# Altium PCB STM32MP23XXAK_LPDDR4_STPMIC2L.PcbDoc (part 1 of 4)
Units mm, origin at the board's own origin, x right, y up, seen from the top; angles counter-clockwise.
Board outline 120 x 79.6 mm, 4 copper layers (Top Layer, Signal Layer 1, Signal Layer 2, Bottom Layer), stack 1.614 mm thick; 156 components, 124 nets, 1131 pads, 692 vias.
Unrouted connection lines stored in the file: 3.
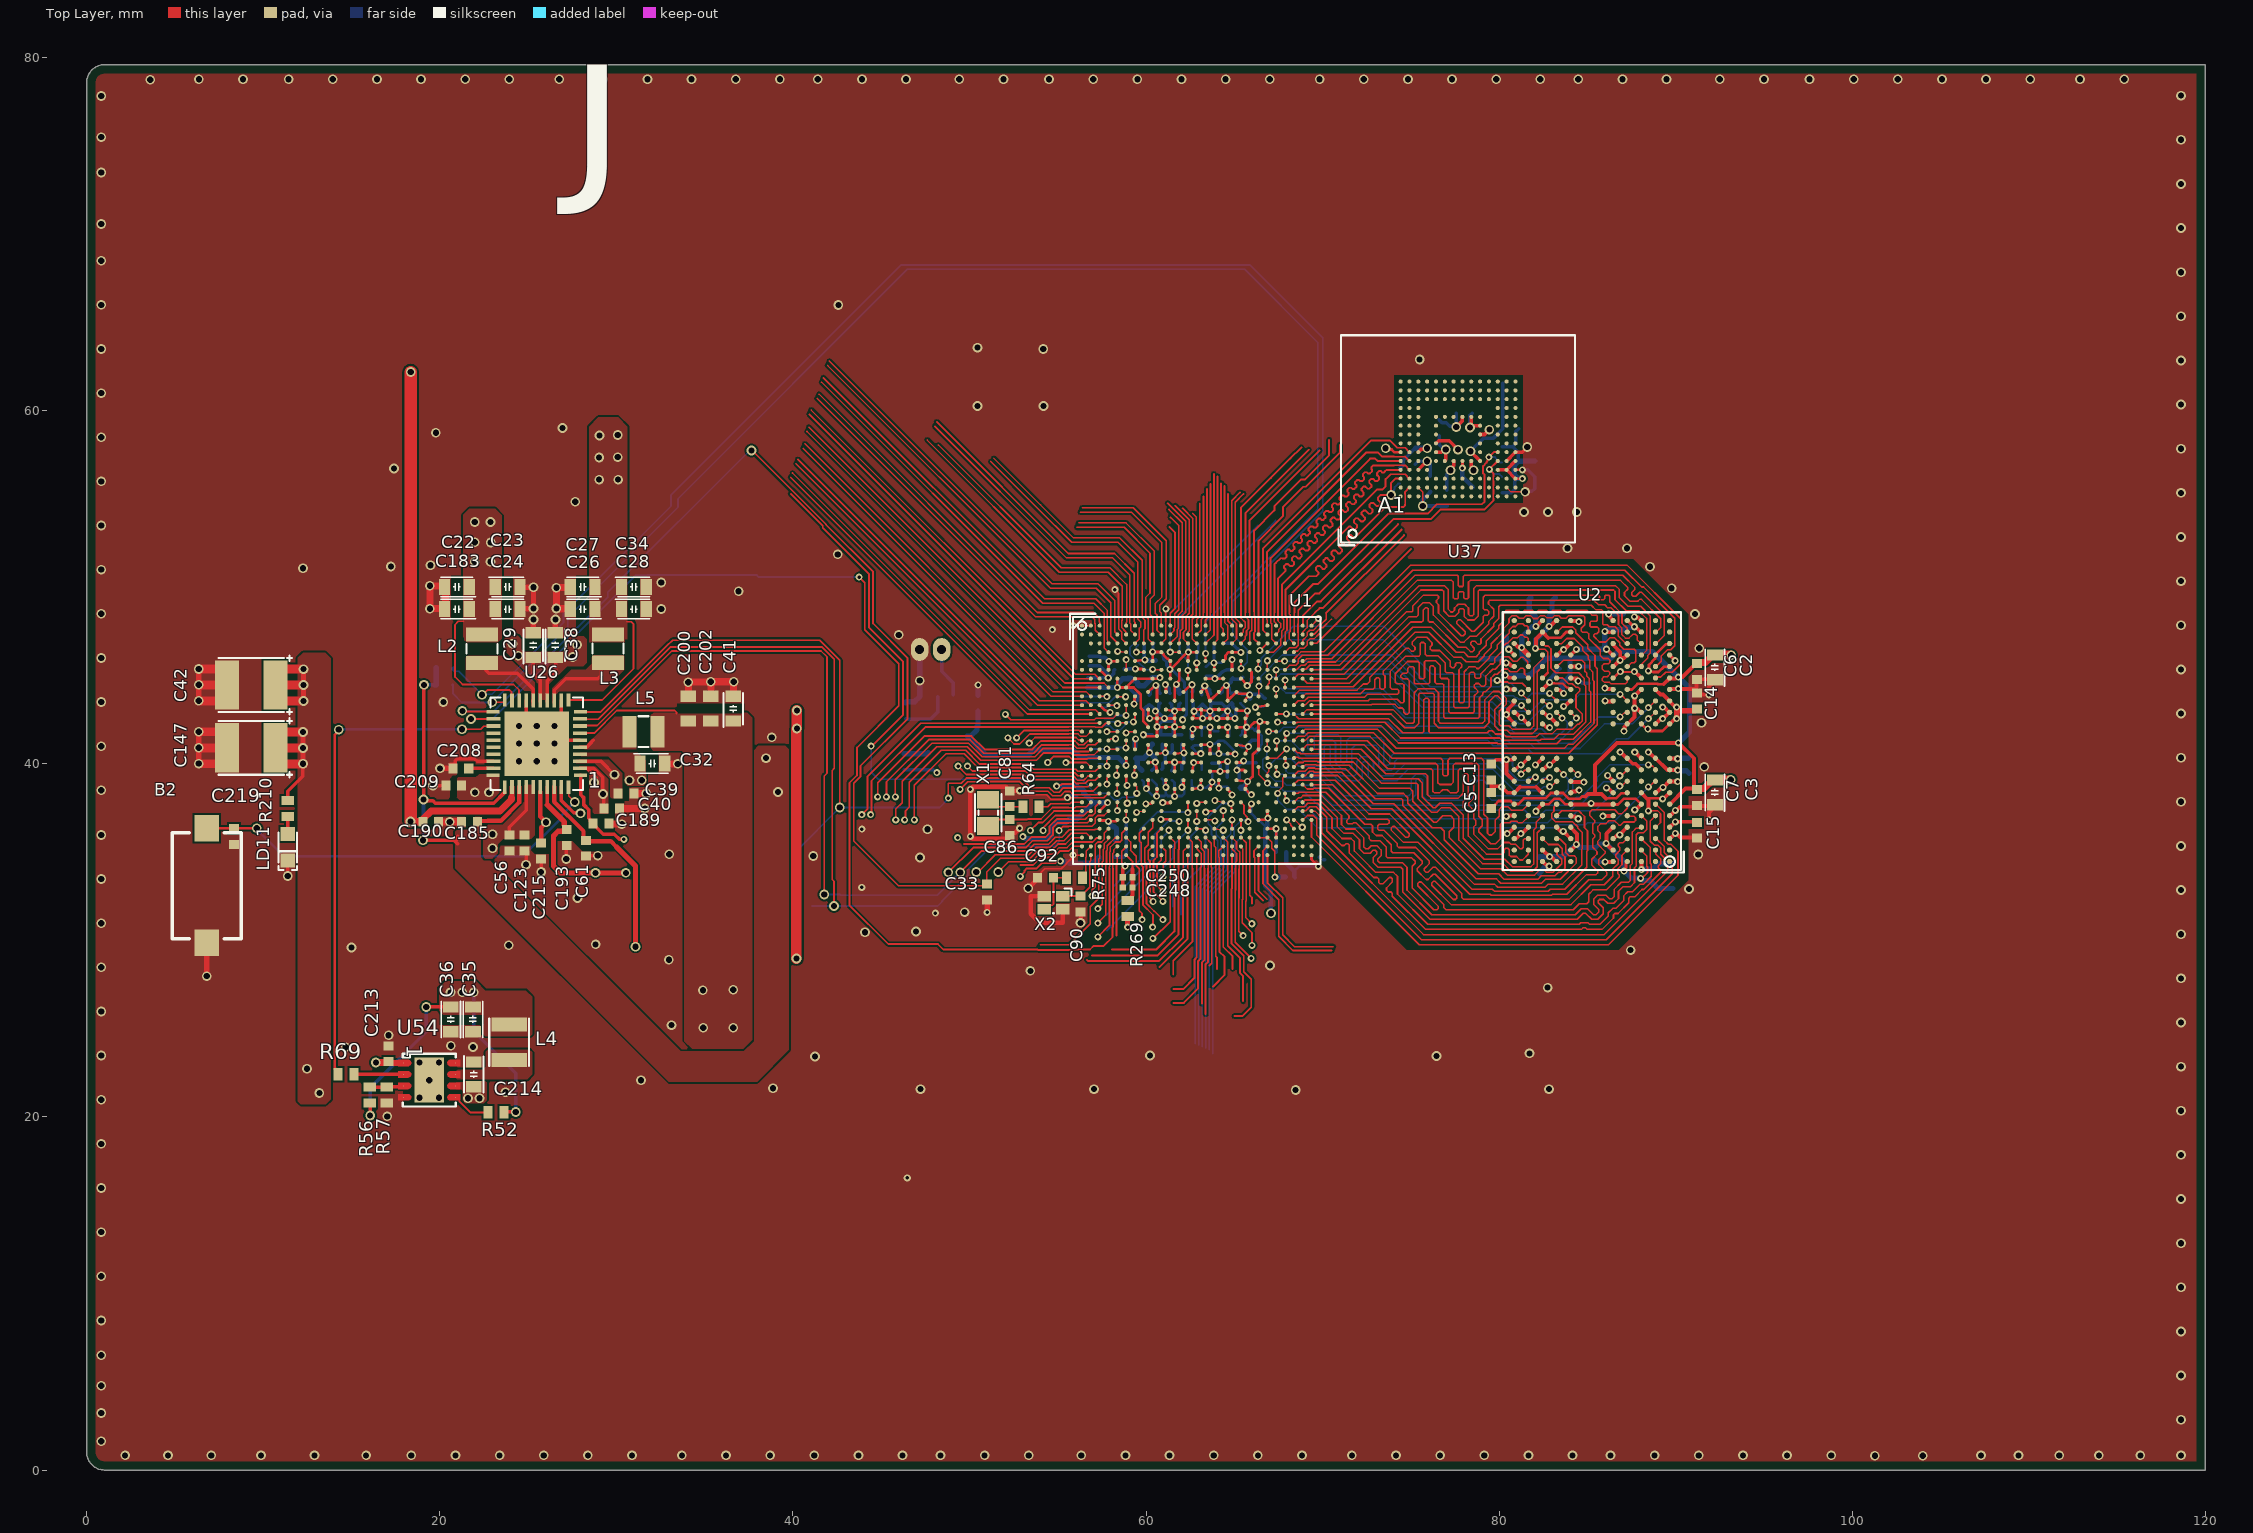
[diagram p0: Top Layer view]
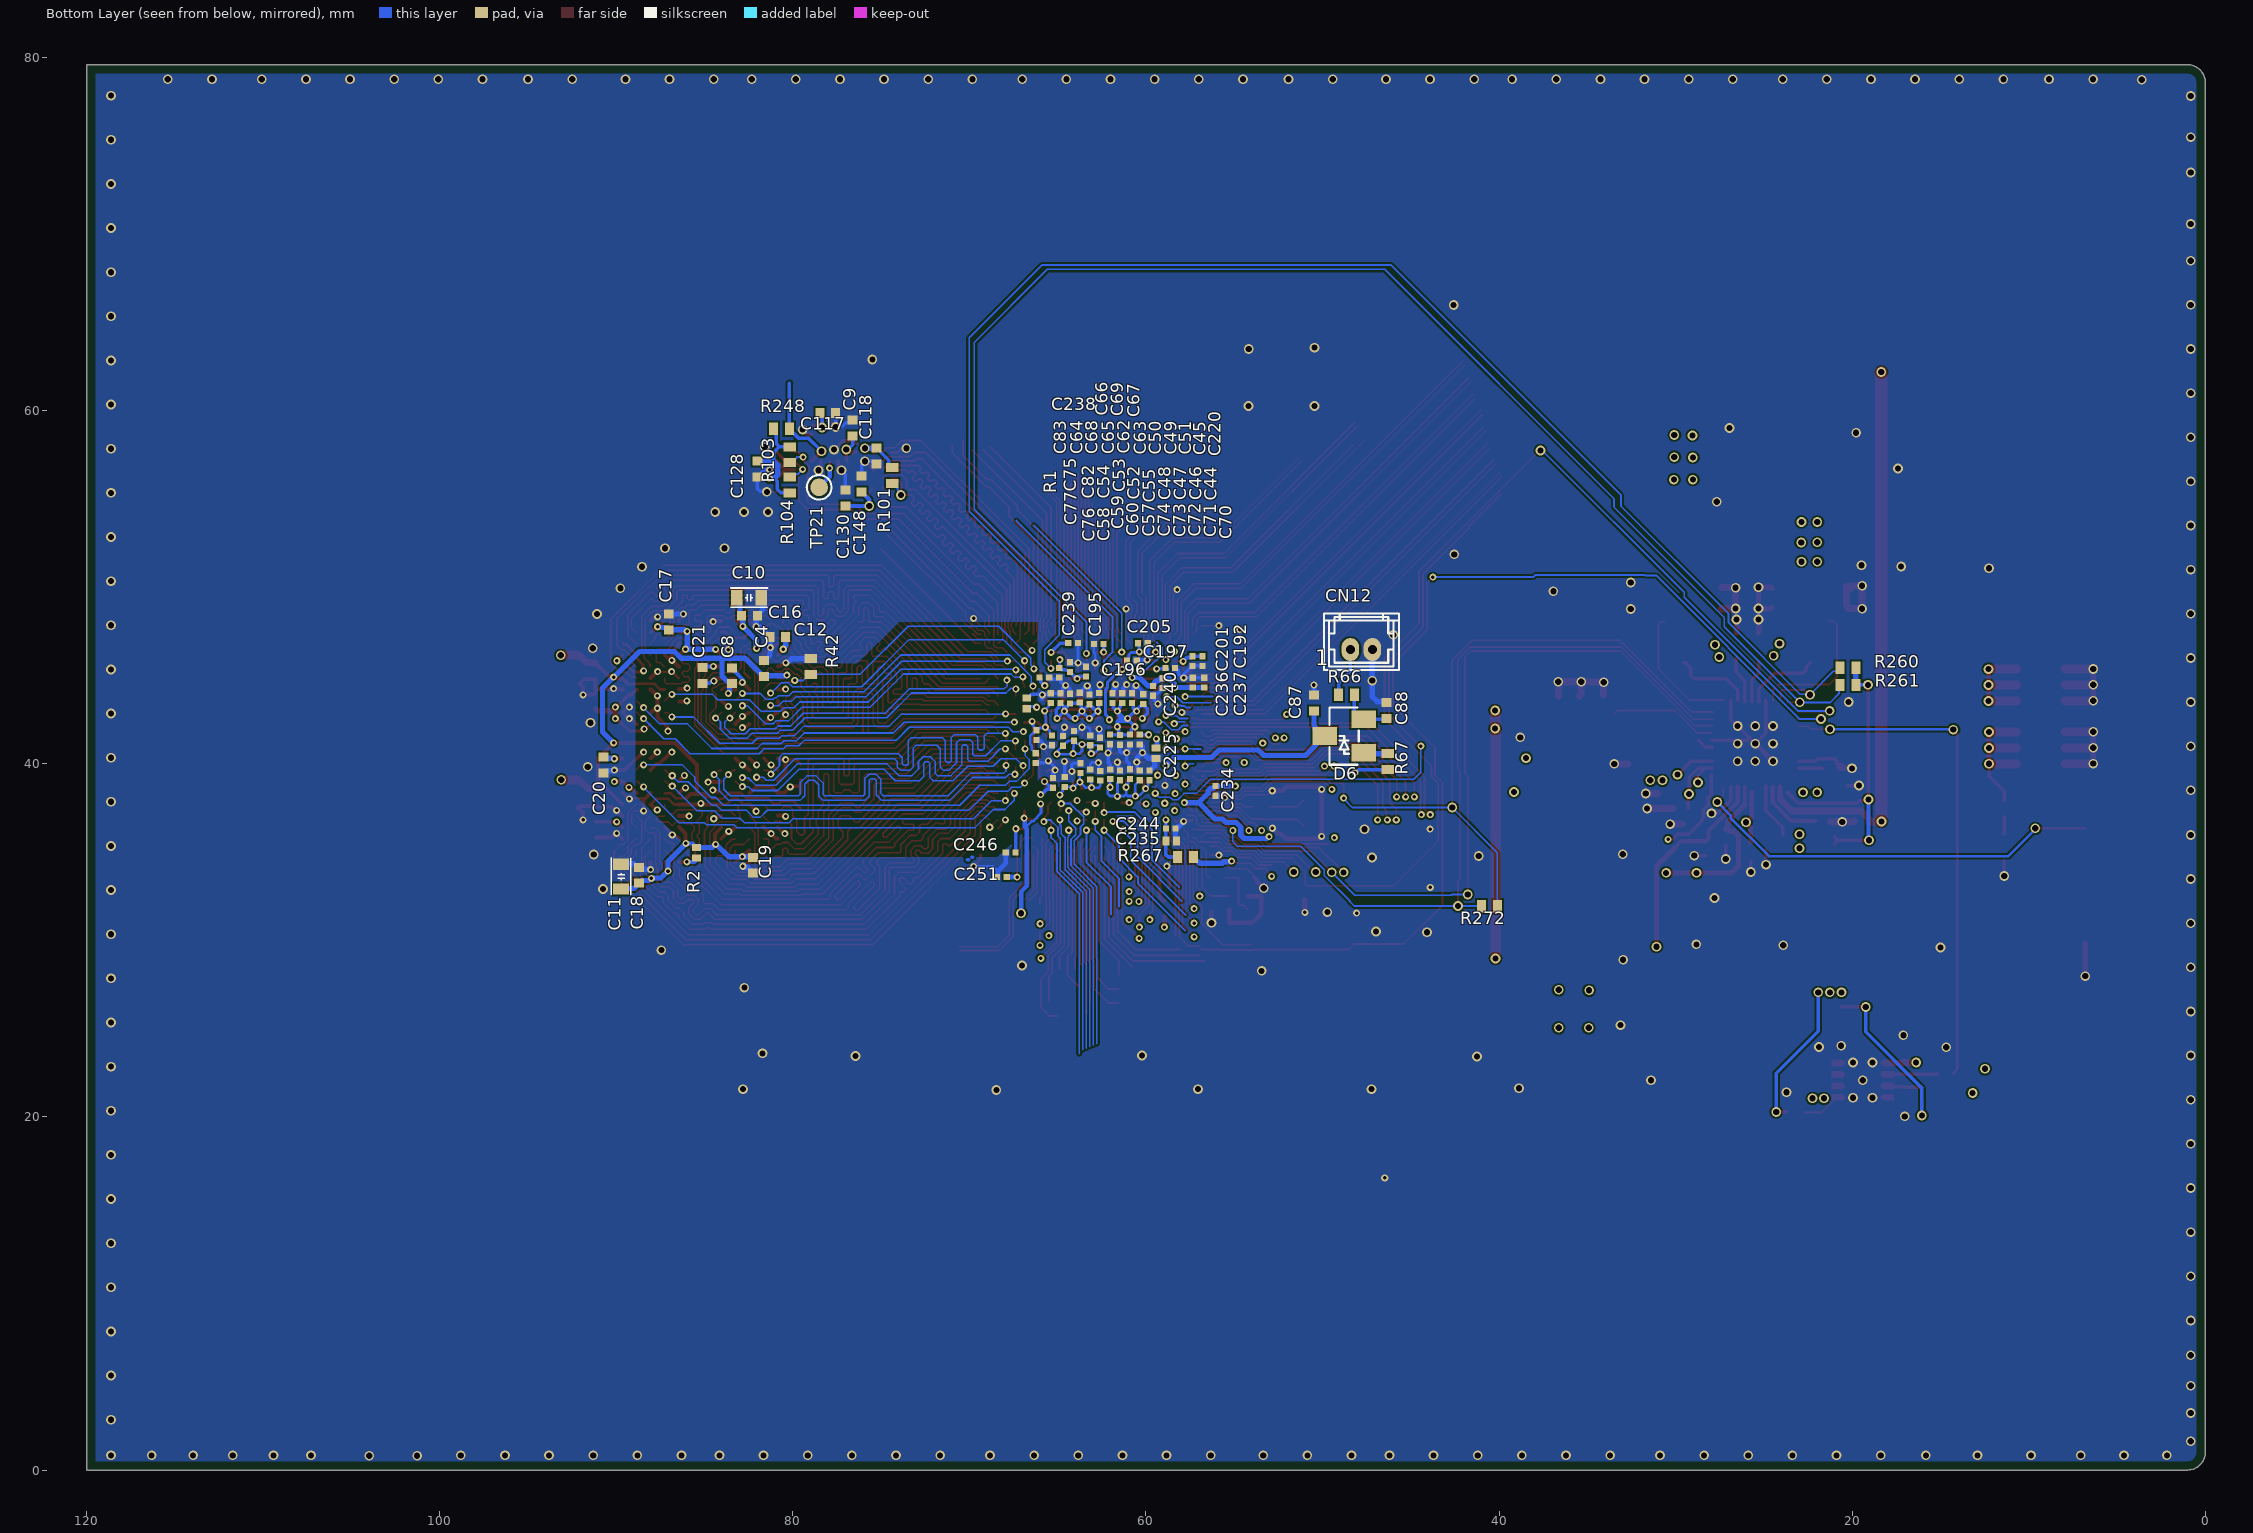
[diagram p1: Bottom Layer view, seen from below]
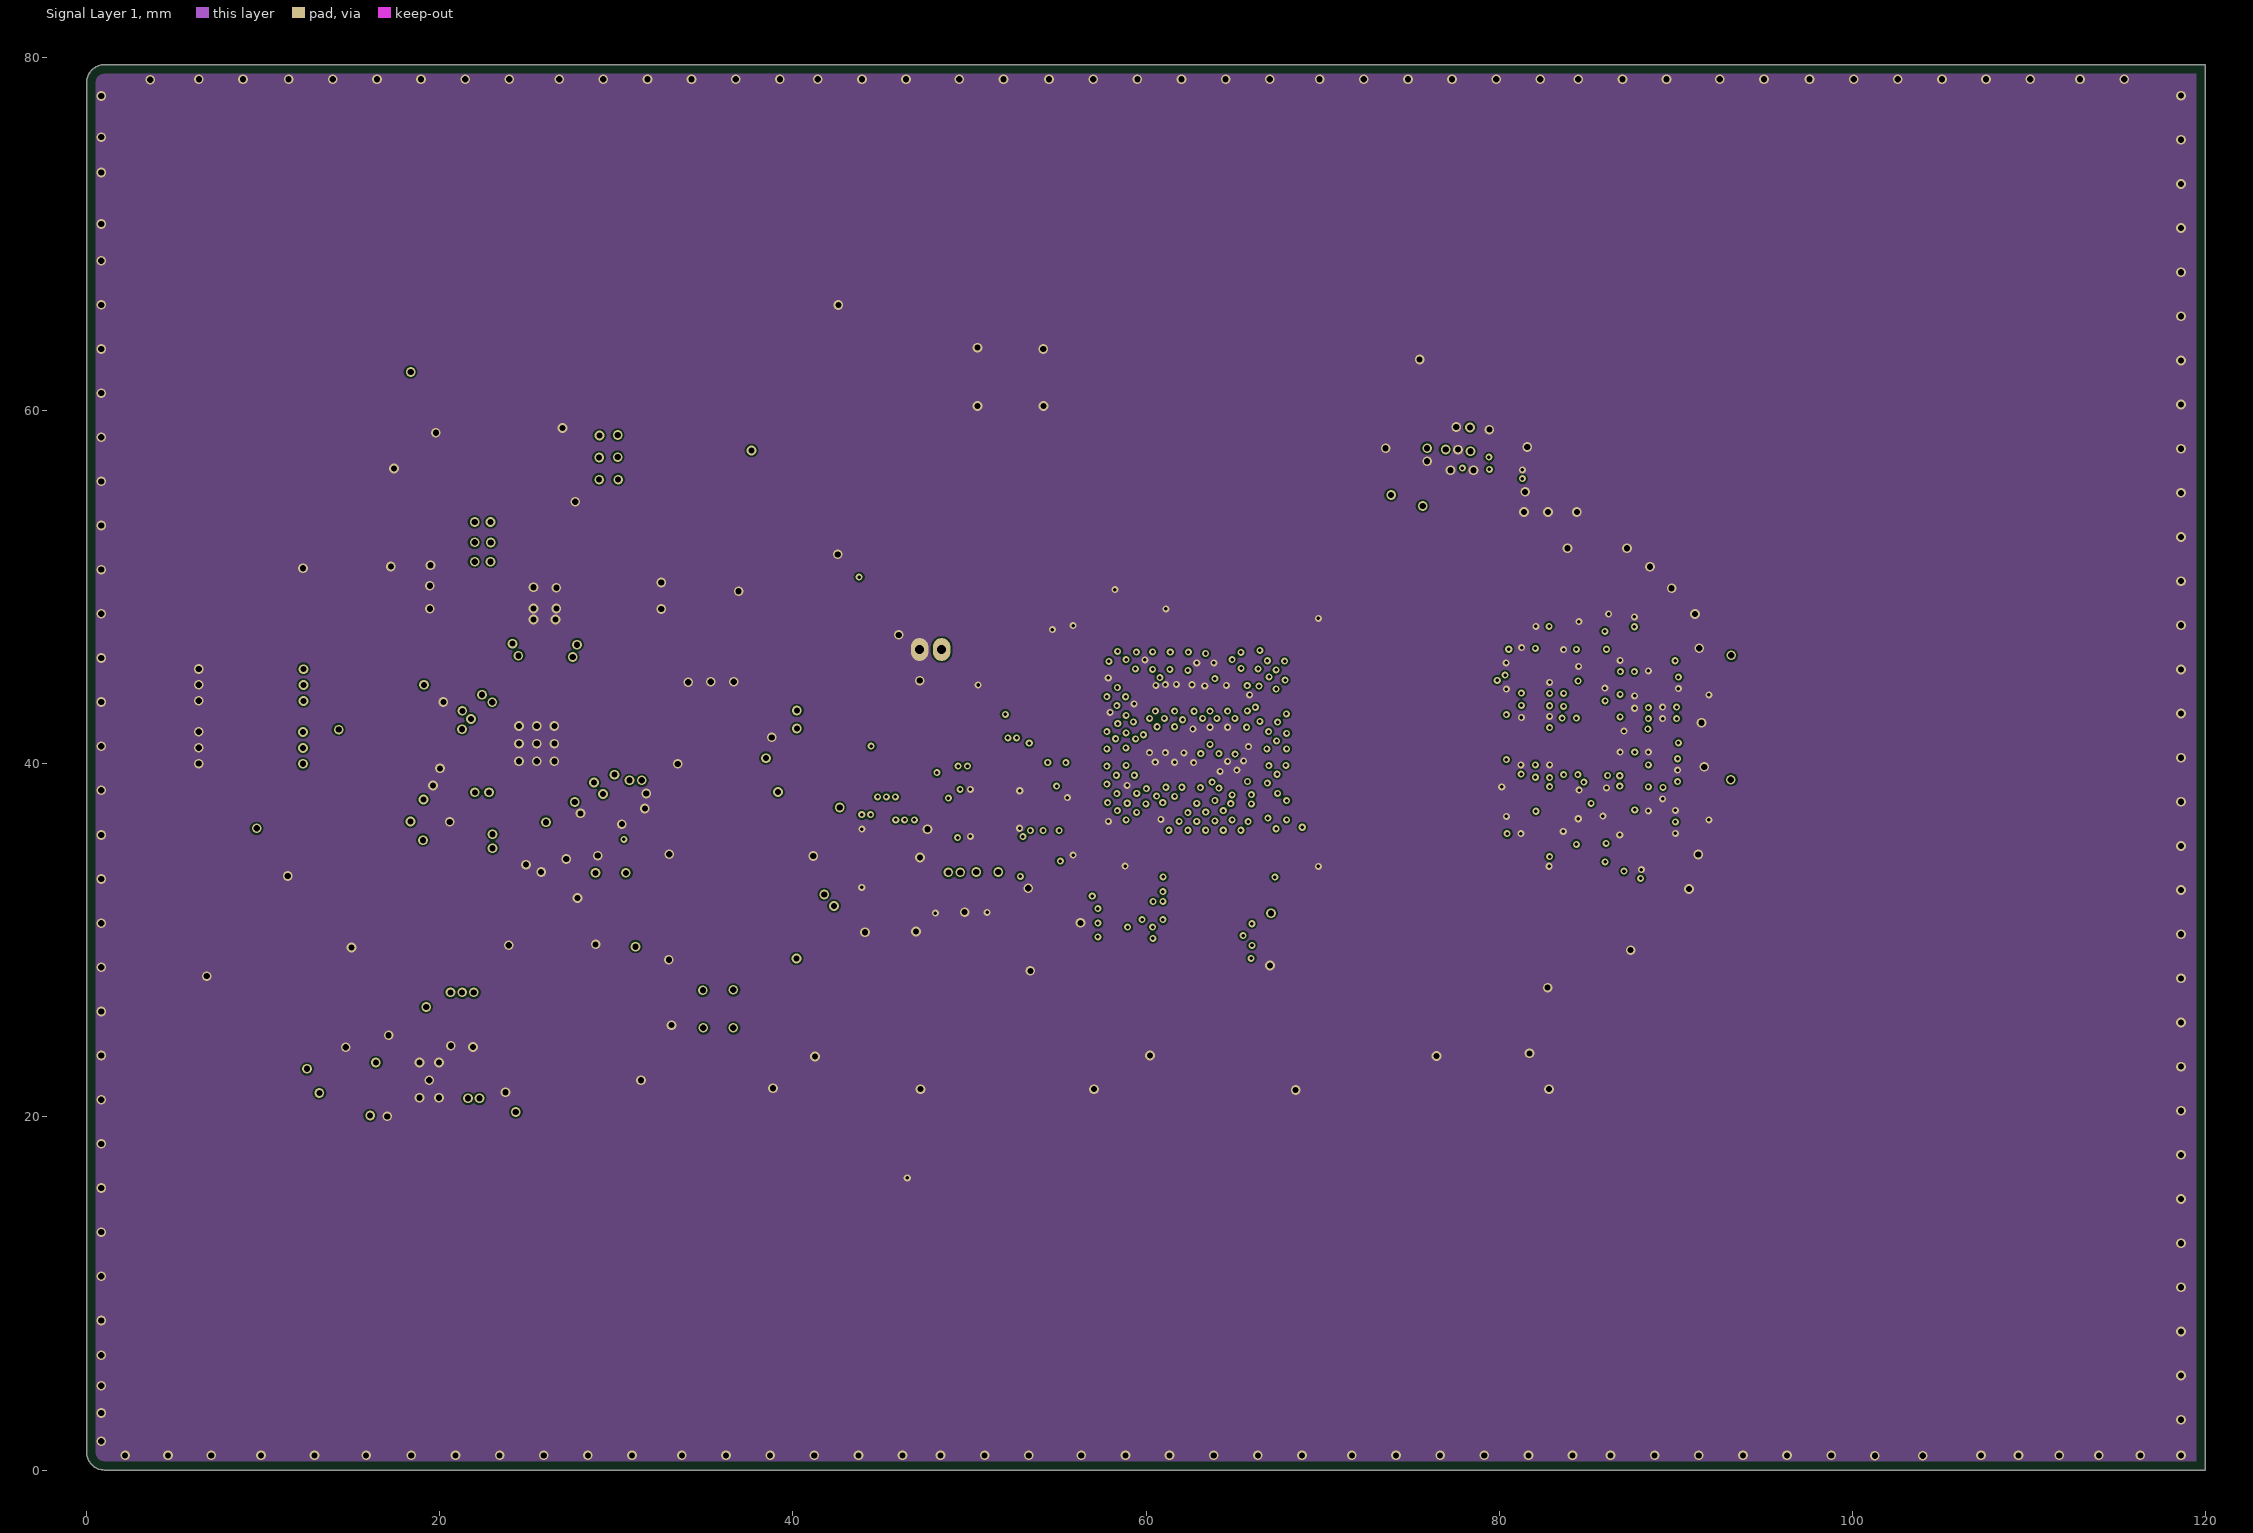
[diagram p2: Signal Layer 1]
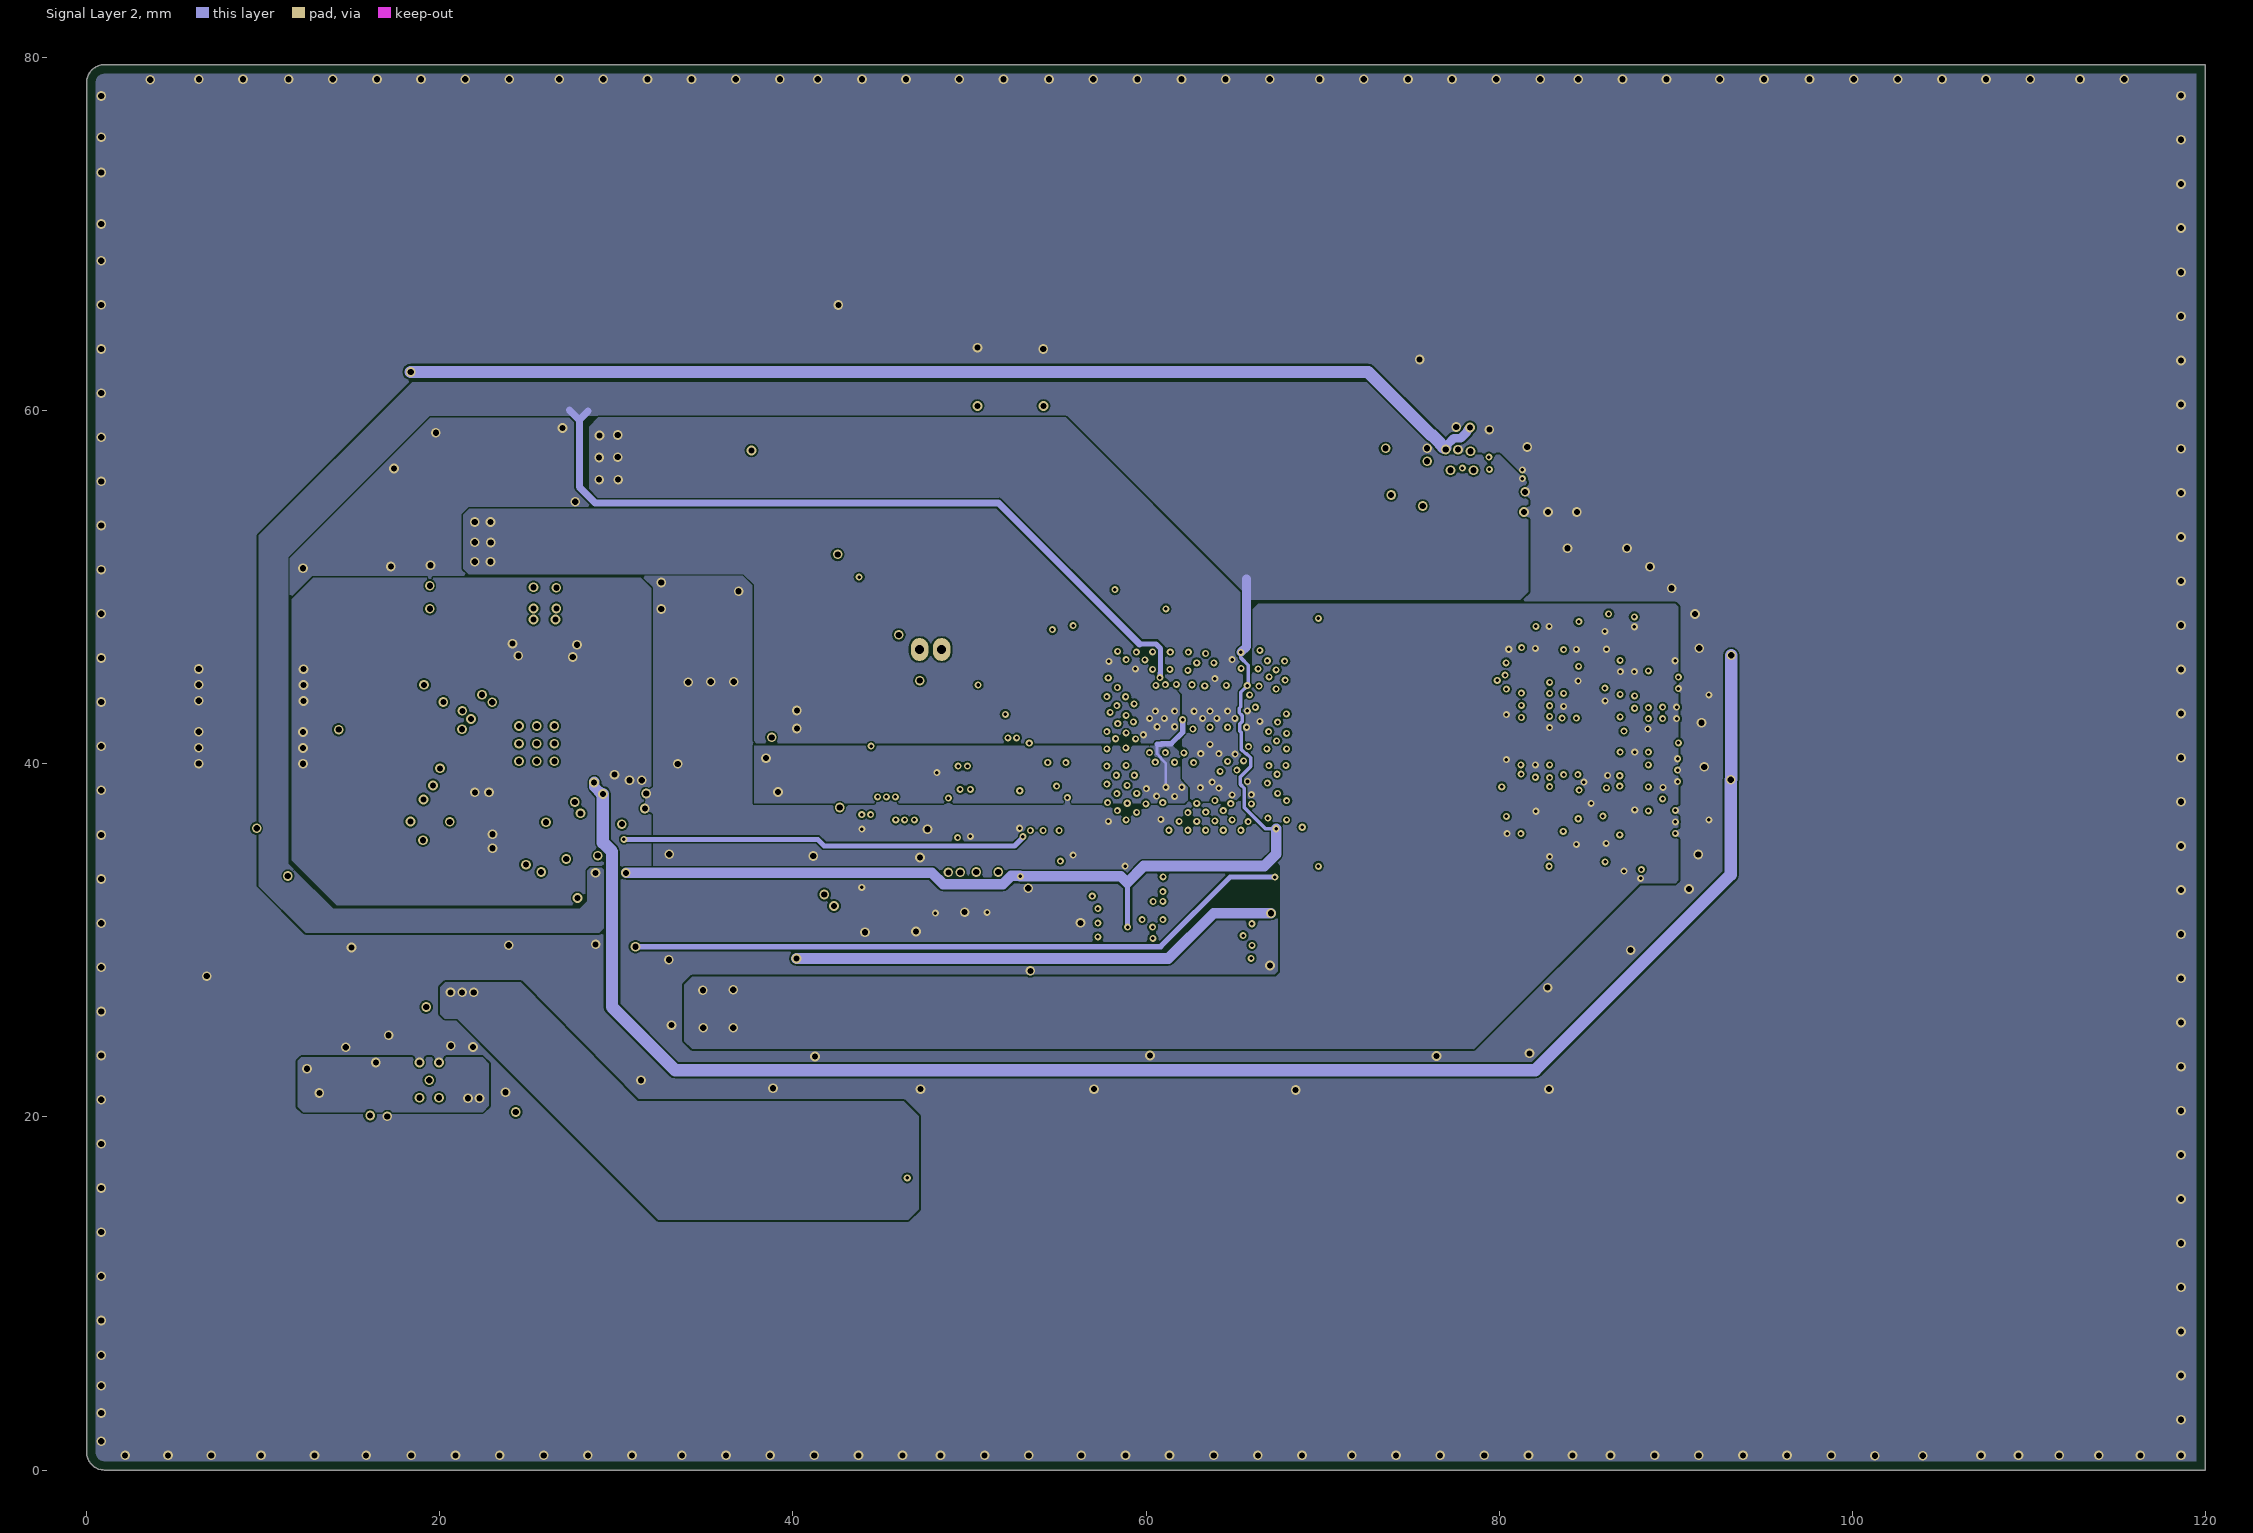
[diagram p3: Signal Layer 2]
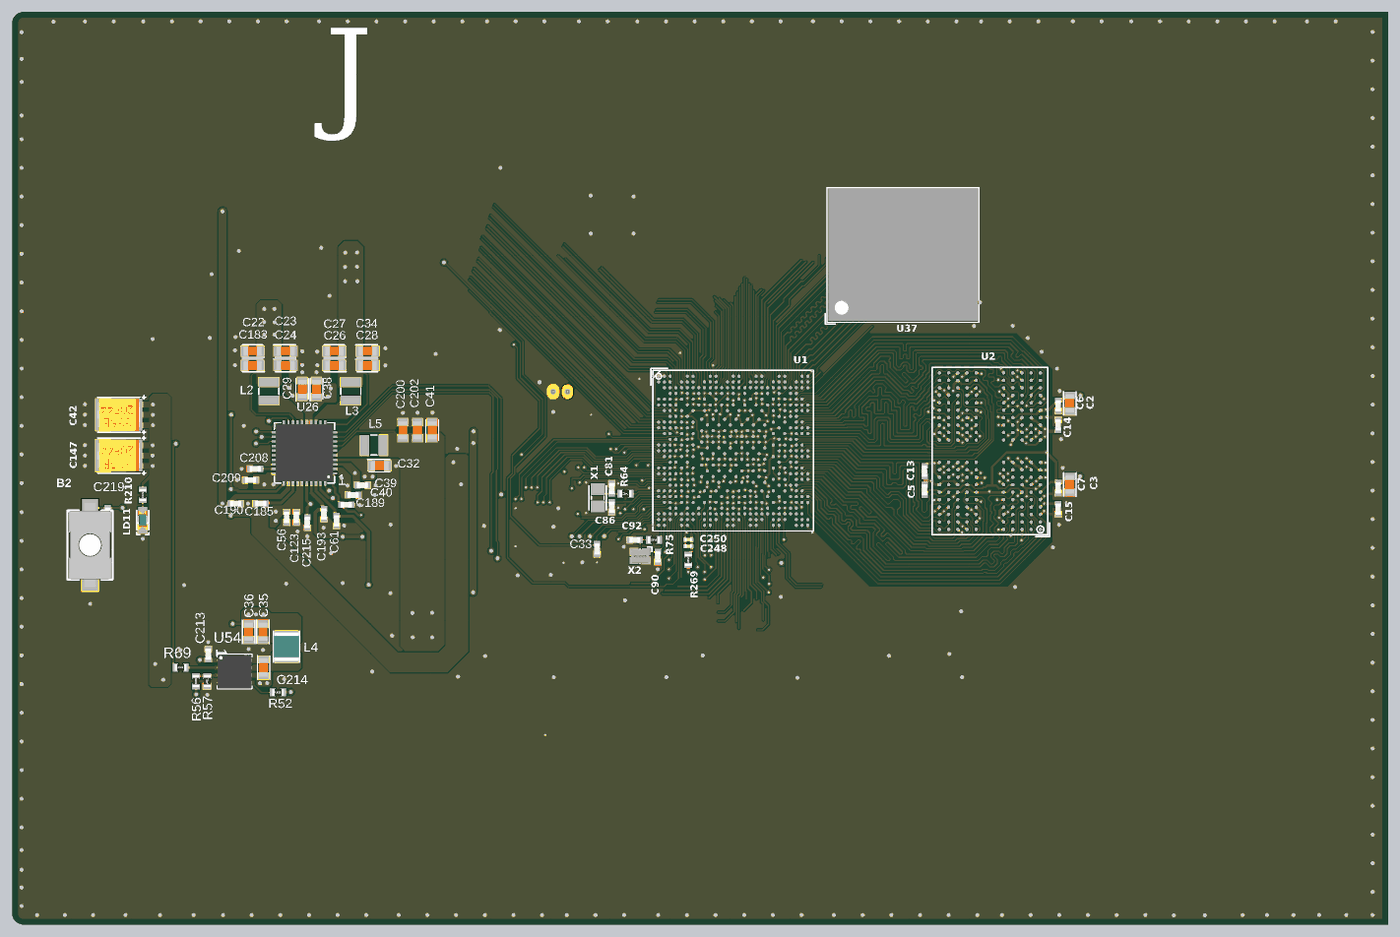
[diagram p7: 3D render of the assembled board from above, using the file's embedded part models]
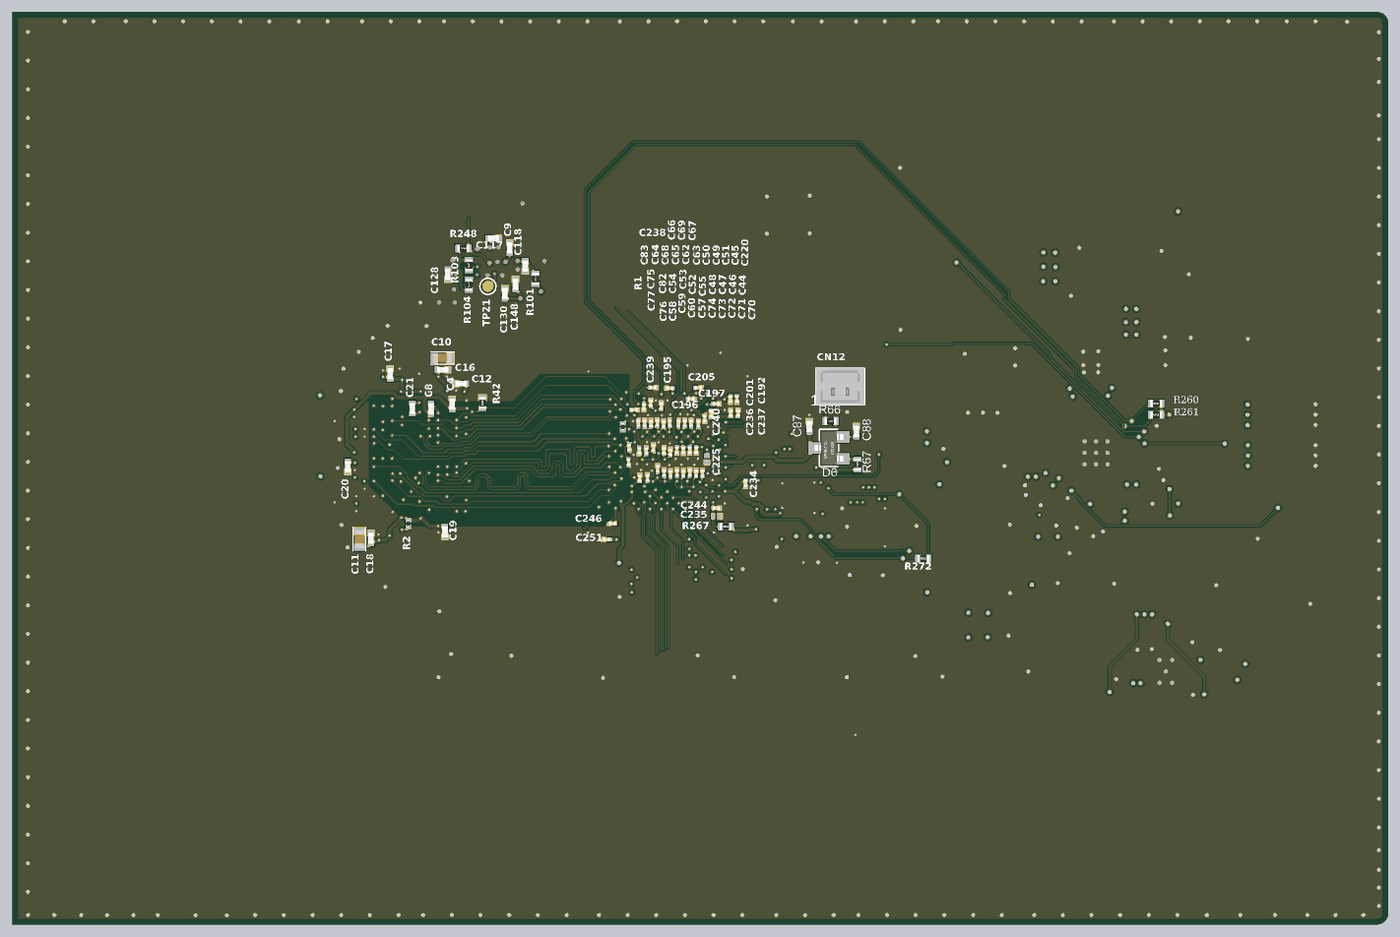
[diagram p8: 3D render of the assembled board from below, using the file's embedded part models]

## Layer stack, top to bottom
Top Solder: solder mask 0.025, Solder Resist, Dk 3.5
Top Layer: signal copper 0.037
Dielectric 1: prepreg 0.07, Dk 3.8
Signal Layer 1: signal copper 0.035
Dielectric 2: core 1.33, Dk 4.3
Signal Layer 2: signal copper 0.035
Dielectric 3: prepreg 0.07, Dk 3.8
Bottom Layer: signal copper 0.037
Bottom Solder: solder mask 0.025, Solder Resist, Dk 3.5

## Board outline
0,1 0,78.6 cw(c1,78.6) 1,79.6 120,79.6 120,0 1,0 cw(c1,1)

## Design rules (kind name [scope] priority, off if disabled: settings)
BoardOutlineClearance Silkscreen [OnLayer('Top Overlay') or OnLayer('Bottom Overlay')] p1: gap=0 ignorepadtopadclearanceinfootprint=FALSE
BoardOutlineClearance [All] p2: gap=0.5 ignorepadtopadclearanceinfootprint=FALSE
Clearance Clearance_Default [All] p1: gap=0.1 ignorepadtopadclearanceinfootprint=TRUE except(0: SMDPad-Hole Via-Hole; 0.09: Track-Track Track-SMDPad; 0.2: Arc-Hole Track-Hole THPad-Hole Fill-Hole Poly-Hole Region-Hole Text-Hole)
ComponentClearance [All] p1: gap=0.2 collisioncheckmode=3 verticalgap=0 showdistances=FALSE
DiffPairsRouting 100H [InDifferentialPairClass('100H')] p1: maxlimit=0.254 minlimit=0.16 mostfreqgap=0.16 toplayer_maxgap=0.16 toplayer_minwidth=0.09 toplayer_maxwidth=0.09 toplayer_prefwidth=0.09 midlayer1_minwidth=0.09 midlayer1_maxwidth=0.381 midlayer1_prefwidth=0.09 midlayer4_minwidth=0.09 midlayer4_maxwidth=0.381 midlayer4_prefwidth=0.09 bottomlayer_maxgap=0.16 bottomlayer_minwidth=0.09 bottomlayer_maxwidth=0.09 bottomlayer_prefwidth=0.09 impedanceprofiledriven=TRUE impedanceprofileid={628B3294-B84C-4222-8D8D-B3EA8745C43E} impedanceprofilevalue=100.000000 maxuncoupledlength=12.7
FanoutControl Fanout_BGA [IsBGA] p1: bgadir=Out bgaviamode=Closest fanoutstyle=Auto fanoutdirection=Alternating viagrid=0.025 // Fanout_BGA (Default Rule)
FanoutControl Fanout_LCC [IsLCC] p2: bgadir=Out bgaviamode=Closest fanoutstyle=Auto fanoutdirection=Alternating viagrid=0.025 // Fanout_LCC (Default Rule)
FanoutControl Fanout_SOIC [IsSOIC] p3: bgadir=Out bgaviamode=Closest fanoutstyle=Auto fanoutdirection=Alternating viagrid=0.025 // Fanout_SOIC (Default Rule)
FanoutControl Fanout_Small [(CompPinCount < 5)] p4: bgadir=Out bgaviamode=Closest fanoutstyle=Auto fanoutdirection=OutThenIn viagrid=0.025 // Fanout_Small (Default Rule)
FanoutControl Fanout_Default [All] p5: bgadir=Out bgaviamode=Closest fanoutstyle=Auto fanoutdirection=Alternating viagrid=0.025 // Fanout_Default (Default Rule)
HoleSize [All] p1: absolutevalues=TRUE maxlimit=10 minlimit=0.1 maxpercent=80.000 minpercent=20.000
HoleToHoleClearance [All] p1: gap=0.25 allowstackedmicrovias=TRUE
MinimumSolderMaskSliver MinimumSolderMaskSliver_SOLDER_BRIDGE [All vs HasFootprint('SOLDER-BRIDGE_R0603-0R')] p1: minsoldermaskwidth=0.07
MinimumSolderMaskSliver [All] p2: minsoldermaskwidth=0.075
NetAntennae [All] p1 off: netantennaetolerance=0
PlaneConnect [All] p1: planeconnectstyle=Direct reliefexpansion=0.508 reliefentries=4 reliefconductorwidth=0.21 reliefairgap=0.21
PolygonConnect PolygonConnect_Default [All] p1: connectstyle=Direct reliefconductorwidth=0.25 reliefentries=4 polygonreliefangle="90 Angle" airgapwidth=0.25
RoomDefinition RoomDefinition_eMMC [False] p1: confinementstyle=ConfineIn formatcopy=TRUE lockcomponents=FALSE outline 74.056,62.109 81.346,62.109 81.346,54.705 74.056,54.705
RoomDefinition RoomDefinition_DDR [False] p2: confinementstyle=ConfineIn formatcopy=TRUE lockcomponents=FALSE outline 79.028,49.26 90.8,49.26 90.8,33.46 79.028,33.46
RoomDefinition U_PMIC [InComponentClass('U_PMIC')] p3: confinementstyle=ConfineIn formatcopy=TRUE lockcomponents=FALSE outline 55.625,48.575 70.125,48.575 70.125,34.075 55.625,34.075
RoutingVias RoutingVias_Default [InDrillLayerPair('Top Layer - Bottom Layer')] p1: holewidth=0.15 width=0.4 viastyle="Through Hole" minholewidth=0.15 minwidth=0.4 maxholewidth=0.35 maxwidth=0.6 useviatemplates=TRUE viatemplateguid#1={8082EAB8-D593-4669-9C8E-234CD125C595} viatemplateguid#2={6F43EA8F-9356-47F3-9E64-8437B01C3073} viatemplateguid#3={9F28DA9E-6088-4B56-A5CF-E6C86A3E97F7} viatemplatename#1=v40h20m0mx0 viatemplatename#2=v40h20m25 viatemplatename#3=v55h35m40mx40
SilkToSilkClearance [All] p1: silktosilkclearance=0.2
SilkToSolderMaskClearance [IsPad] p1: minsilkscreentomaskgap=0.015 clearancetoexposedcopper=TRUE
SolderMaskExpansion [All] p1: expansion=0.1 istentingtop=FALSE
SupplyNets "Schematic Supply Nets_5" [InNet('VDD_free')] p1: voltage=0.000
SupplyNets "Schematic Supply Nets_18" [InNet('3V3')] p2: voltage=0.000
SupplyNets "Schematic Supply Nets_17" [InNet('VDDIO')] p3: voltage=0.000
SupplyNets "Schematic Supply Nets_16" [InNet('VDDCPUGPU')] p4: voltage=0.000
SupplyNets "Schematic Supply Nets_15" [InNet('VDD3V3_USB')] p5: voltage=0.000
SupplyNets "Schematic Supply Nets_11" [InNet('GND')] p6: voltage=0.000
SupplyNets "Schematic Supply Nets_10" [InNet('VREF+')] p7: voltage=0.000
SupplyNets "Schematic Supply Nets_9" [InNet('VDD1_DDR')] p8: voltage=0.000
SupplyNets "Schematic Supply Nets_7" [InNet('VDD2_DDR')] p9: voltage=0.000
SupplyNets "Schematic Supply Nets_6" [InNet('VDDA1V8_AON')] p10: voltage=0.000
SupplyNets "Schematic Supply Nets_4" [InNet('5V_VIN')] p11: voltage=0.000
SupplyNets "Schematic Supply Nets_3" [InNet('VBAT')] p12: voltage=0.000
SupplyNets "Schematic Supply Nets_2" [InNet('VDDCORE')] p13: voltage=0.000
SupplyNets "Schematic Supply Nets_1" [InNet('1V8')] p14: voltage=0.000
SupplyNets "Schematic Supply Nets" [InNet('VDD_EMMC')] p15: voltage=0.000
UnRoutedNet [All] p1 off:
ViasUnderSMD [InPadClass('PC_VIAS-IN-PAD_OK')] p1: allowed=TRUE
Width Width_SINGLE_50R [InNetClass('50H')] p1 off: maxlimit=0.199 minlimit=0.078 preferedwidth=0.199 toplayer_minwidth=0.09 toplayer_maxwidth=0.11 toplayer_prefwidth=0.11 bottomlayer_minwidth=0.11 bottomlayer_maxwidth=0.11 bottomlayer_prefwidth=0.11 impedanceprofiledriven=TRUE impedanceprofileid={152E730A-FDA4-4006-BF82-0EE0D5C1A339} impedanceprofilevalue=50.000000 minimp=50.000000 maximp=50.000000 favimp=50.000000
Width Width_SINGLE_DDR_55R [InNetClass('55H')] p2 off: maxlimit=0.199 minlimit=0.078 preferedwidth=0.199 toplayer_minwidth=0.09 toplayer_maxwidth=0.09 toplayer_prefwidth=0.09 bottomlayer_minwidth=0.09 bottomlayer_maxwidth=0.09 bottomlayer_prefwidth=0.09 impedanceprofiledriven=TRUE impedanceprofileid={D5948A69-504E-4D29-B9E5-77B49DDD78E4} impedanceprofilevalue=55.000000 minimp=50.000000 maximp=50.000000 favimp=50.000000
Width Width_Default [InNet('GND')] p3: maxlimit=10 minlimit=0.09 preferedwidth=0.3 toplayer_prefwidth=0.09 bottomlayer_prefwidth=0.09 minimp=50.000000 maximp=50.000000 favimp=50.000000
15 further rules are at their usual default settings.

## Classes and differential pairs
component class U_LPDDR4: C2 C3 C4 C5 C6 C7 C8 C10 C11 C12 C13 C14 C15 C16 C17 C18 C19 C20 C21 R1 R2 R42 U2
net class 100H: DDR_CLK_A_N DDR_CLK_A_P DDR_CLK_B_N DDR_CLK_B_P DDR_DQS0_A_N DDR_DQS0_A_P DDR_DQS0_B_N DDR_DQS0_B_P DDR_DQS1_A_N DDR_DQS1_A_P DDR_DQS1_B_N DDR_DQS1_B_P
differential pair class 100H: CLKA CLKB DQS0A DQS0B DQS1A DQS1B
net class eMMC.SDMMC2_D[0..7]: eMMC.SDMMC2_CK eMMC.SDMMC2_CMD eMMC.SDMMC2_D0 eMMC.SDMMC2_D1 eMMC.SDMMC2_D2 eMMC.SDMMC2_D3 eMMC.SDMMC2_D4 eMMC.SDMMC2_D5 eMMC.SDMMC2_D6 eMMC.SDMMC2_D7
component class U_eMMC: C9 C117 C118 C128 C130 C148 R101 R103 R104 R248 TP21 U37
component class "U_STM32MP23XXAK I_Os": C33 C81 C86 C90 C92 R64 R75 R260 R261 R272 U1 X1 X2
component class "U_STM32MP23XXAK Power": C44 C45 C46 C47 C48 C49 C50 C51 C52 C53 C54 C55 C57 C58 C59 C60 C62 C63 C64 C65 C66 C67 C68 C69 C70 C71 C72 C73 C74 C75 C76 C77 C82 C83 C87 C88 C192 C195 C196 C197 C201 C205 C220 C225 C234 C235 C236 C237 C238 C239 C240 C244 C246 C248 C250 C251 CN12 D6 R66 R67 R267 R269
component class U_PMIC: B2 C22 C23 C24 C26 C27 C28 C29 C32 C34 C35 C36 C38 C39 C40 C41 C42 C56 C61 C123 C147 C183 C185 C189 C190 C193 C200 C202 C208 C209 C213 C214 C215 C219 L2 L3 L4 L5 LD11 R52 R56 R57 R69 R210 U26 U54
differential pair CLKB: +DDR_CLK_B_P -DDR_CLK_B_N
differential pair CLKA: +DDR_CLK_A_P -DDR_CLK_A_N
differential pair DQS1B: +DDR_DQS1_B_P -DDR_DQS1_B_N
differential pair DQS0B: +DDR_DQS0_B_P -DDR_DQS0_B_N
differential pair DQS1A: +DDR_DQS1_A_P -DDR_DQS1_A_N
differential pair DQS0A: +DDR_DQS0_A_P -DDR_DQS0_A_N

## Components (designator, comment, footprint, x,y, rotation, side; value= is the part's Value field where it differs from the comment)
B2 "SW_PUSH_SMD_2P" SWI_WE_434121025816 6.795,33.104 r90 top value=434121025816
C2 "Capacitor" C0603 92.225,45.46 r90 top value=10uF
C3 "Capacitor" C0603 92.225,38.385 r90 top value=10uF
C4 "100nF" C0402 81.63,45.397 r90 bottom
C5 "100nF" C0402 79.559,37.929 r90 top
C6 "100nF" C0402 91.209,45.24 r270 top
C7 "100nF" C0402 91.209,38.09 r270 top
C8 "100nF" C0402 83.461,44.99 r90 bottom
C9 "Capacitor" C0402 76.615,59.03 r270 bottom value=100nF
C10 "Capacitor" C0603 82.486,49.415 r0 bottom value=10uF
C11 "Capacitor" C0603 89.736,33.615 r270 bottom value=10uF
C12 "100nF" C0402 80.861,47.18 r0 bottom
C13 "100nF" C0402 79.559,39.529 r270 top
C14 "100nF" C0402 91.209,43.565 r90 top
C15 "100nF" C0402 91.209,36.24 r270 top
C16 "100nF" C0402 82.461,48.39 r180 bottom
C17 "100nF" C0402 87.036,48.04 r90 bottom
C18 "100nF" C0402 88.711,33.69 r90 bottom
C19 "100nF" C0402 82.261,34.255 r270 bottom
C20 "100nF" C0402 90.736,39.94 r270 bottom
C21 "100nF" C0402 85.111,45.015 r90 bottom
C22 "Capacitor" C0603 20.963,50.019 r0 top value=22uF
C23 "Capacitor" C0603 23.838,50.019 r180 top value=22uF
C24 "Capacitor" C0603 23.838,48.769 r180 top value=22uF
C26 "Capacitor" C0603 28.088,48.769 r0 top value=22uF
C27 "Capacitor" C0603 28.088,50.019 r0 top value=22uF
C28 "Capacitor" C0603 30.988,48.769 r180 top value=22uF
C29 "Capacitor" C0603 25.288,46.719 r270 top value=10uF
C32 "Capacitor" C0603 32.038,40.019 r180 top value=10uF
C33 "Capacitor" C0402 51,32.75 r90 top value=10nF
C34 "Capacitor" C0603 30.988,50.019 r180 top value=22uF
C35 "Capacitor" C0603 21.876,25.532 r90 top value=22uF
C36 "Capacitor" C0603 20.626,25.532 r90 top value=22uF
C38 "Capacitor" C0603 26.538,46.719 r270 top value=10uF
C39 "Capacitor" C0402 30.538,38.319 r180 top value=1uF
C40 "Capacitor" C0402 29.738,37.469 r0 top value=4.7uF
C41 "Capacitor" C0603 36.625,43.125 r270 top value=22uF
C42 "CAP_POL" CPOL_TCJ-B_1210_H210 9.311,44.468 r180 top value=100uF
C44 "1uF" C0201_MURATA_GRM033_H0P3 60.351,41.38 r270 bottom
C45 "1uF" C0201_MURATA_GRM033_H0P3 60.16,43.67 r270 bottom
C46 "1uF" C0201_MURATA_GRM033_H0P3 60.915,41.38 r90 bottom
C47 "1uF" C0201_MURATA_GRM033_H0P3 61.476,41.356 r270 bottom
C48 "1uF" C0201_MURATA_GRM033_H0P3 62.038,41.382 r90 bottom
C49 "1uF" C0201_MURATA_GRM033_H0P3 61.35,43.725 r270 bottom
C50 "1uF" C0201_MURATA_GRM033_H0P3 61.9,43.725 r270 bottom
C51 "1uF" C0201_MURATA_GRM033_H0P3 60.8,43.725 r270 bottom
C52 "1uF" C0201_MURATA_GRM033_H0P3 63.162,41.332 r270 bottom
C53 "1uF" C0201_MURATA_GRM033_H0P3 64.083,41.581 r270 bottom
C54 "1uF" C0201_MURATA_GRM033_H0P3 64.706,41.304 r270 bottom
C55 "1uF" C0201_MURATA_GRM033_H0P3 62.6,41.2 r270 bottom
C56 "Capacitor" C0402 23.938,35.519 r90 top value=1uF
C57 "1uF" C0201_MURATA_GRM033_H0P3 62.592,39.328 r270 bottom
C58 "1uF" C0201_MURATA_GRM033_H0P3 64.607,38.972 r270 bottom
C59 "1uF" C0201_MURATA_GRM033_H0P3 63.714,39.761 r270 bottom
C60 "1uF" C0201_MURATA_GRM033_H0P3 63.154,39.397 r270 bottom
C61 "Capacitor" C0402 28.288,35.219 r270 top value=4.7uF
C62 "1uF" C0201_MURATA_GRM033_H0P3 63.2,43.65 r90 bottom
C63 "1uF" C0201_MURATA_GRM033_H0P3 62.65,43.73 r270 bottom
C64 "1uF" C0201_MURATA_GRM033_H0P3 64.85,43.725 r270 bottom
C65 "1uF" C0201_MURATA_GRM033_H0P3 63.75,43.75 r90 bottom
C66 "1uF" C0201_MURATA_GRM033_H0P3 64.915,45.16 r90 bottom
C67 "1uF" C0201_MURATA_GRM033_H0P3 63.4,45.225 r270 bottom
C68 "1uF" C0201_MURATA_GRM033_H0P3 64.3,43.7 r270 bottom
C69 "1uF" C0201_MURATA_GRM033_H0P3 64.305,45.477 r270 bottom
C70 "1uF" C0201_MURATA_GRM033_H0P3 59.805,39.35 r90 bottom
C71 "1uF" C0201_MURATA_GRM033_H0P3 60.355,39.35 r270 bottom
C72 "1uF" C0201_MURATA_GRM033_H0P3 60.905,39.423 r270 bottom
C73 "1uF" C0201_MURATA_GRM033_H0P3 61.467,39.349 r90 bottom
C74 "1uF" C0201_MURATA_GRM033_H0P3 62.03,39.408 r270 bottom
C75 "1uF" C0201_MURATA_GRM033_H0P3 66.205,41.625 r90 bottom
C76 "1uF" C0201_MURATA_GRM033_H0P3 65.274,38.923 r270 bottom
C77 "1uF" C0201_MURATA_GRM033_H0P3 66.25,40.325 r270 bottom
C81 "Capacitor" C0402 52.285,38.025 r90 top value=6.8pF
C82 "1uF" C0201_MURATA_GRM033_H0P3 65.325,41.325 r90 bottom
C83 "1uF" C0201_MURATA_GRM033_H0P3 65.395,43.725 r270 bottom
C86 "Capacitor" C0402 52.285,36.4 r270 top value=6.8pF
C87 "Capacitor" C0402 50.485,43.438 r270 bottom value=100nF
C88 "Capacitor" C0402 46.382,43.015 r270 bottom value=2.2uF
C90 "Capacitor" C0402 56.293,32.06 r90 top value=6.8pF
C92 "Capacitor" C0402 54.309,33.546 r180 top value=6.8pF
C117 "Capacitor" C0402 78.025,59.864 r0 bottom value=2.2uF
C118 "Capacitor" C0402 75.26,57.43 r90 bottom value=100nF
C123 "Capacitor" C0402 24.788,35.519 r90 top value=1uF
C128 "Capacitor" C0402 82.015,56.705 r90 bottom value=2.2uF
C130 "Capacitor" C0402 77.027,55.055 r270 bottom value=100nF
C147 "CAP_POL" CPOL_TCJ-B_1210_H210 9.311,40.906 r180 top value=100uF
C148 "Capacitor" C0402 76.11,55.855 r270 bottom value=2.2uF
C183 "Capacitor" C0603 20.963,48.769 r0 top value=22uF
C185 "Capacitor" C0402 21.688,36.719 r180 top value=4.7uF
C189 "Capacitor" C0402 29.138,36.619 r0 top value=4.7uF
C190 "Capacitor" C0402 19.488,36.719 r0 top value=4.7uF
C192 "Capacitor" C0201_MURATA_GRM033_H0P3 56.8,45.825 r90 bottom value=100nF
C193 "Capacitor" C0402 27.188,35.819 r270 top value=4.7uF
C195 "Capacitor" C0201_MURATA_GRM033_H0P3 62.675,46.787 r180 bottom value=100nF
C196 "Capacitor" C0201_MURATA_GRM033_H0P3 60.8,45.85 r0 bottom value=100nF
C197 "Capacitor" C0201_MURATA_GRM033_H0P3 58.625,45.425 r0 bottom value=100nF
C200 "Capacitor" C0603 34.075,43.125 r270 top value=22uF
C201 "Capacitor" C0201_MURATA_GRM033_H0P3 57.375,45.825 r90 bottom value=100nF
C202 "Capacitor" C0603 35.35,43.125 r270 top value=22uF
C205 "Capacitor" C0201_MURATA_GRM033_H0P3 60.177,46.829 r0 bottom value=100nF
C208 "Capacitor" C0402 21.188,39.744 r0 top value=4.7uF
C209 "Capacitor" C0402 20.788,38.769 r0 top value=4.7uF
C213 "Capacitor" C0402 17.101,23.582 r270 top value=1uF
C214 "Capacitor" C0603 21.926,22.407 r270 top value=10uF
C215 "Capacitor" C0402 25.738,35.069 r90 top value=4.7uF
C219 "Capacitor" C0402 8.34,35.883 r90 top value=10nF
C220 "Capacitor" C0201_MURATA_GRM033_H0P3 59.609,44.131 r90 bottom value=100nF
C225 "Capacitor" C0201_H0P5 59.425,40.6 r90 bottom value=4.7uF
C234 "Capacitor" C0201_MURATA_GRM033_H0P3 56.064,38.473 r90 bottom value=100nF
C235 "Capacitor" C0201_H0P5 58.575,35.625 r0 bottom value=2.2uF
C236 "Capacitor" C0201_MURATA_GRM033_H0P3 57.35,44.6 r270 bottom value=100nF
C237 "Capacitor" C0201_MURATA_GRM033_H0P3 56.696,44.605 r270 bottom value=100nF
C238 "Capacitor" C0201_MURATA_GRM033_H0P3 65.758,44.894 r0 bottom value=100nF
C239 "Capacitor" C0201_MURATA_GRM033_H0P3 64.125,46.837 r0 bottom value=100nF
C240 "Capacitor" C0201_MURATA_GRM033_H0P3 59.05,44.575 r90 bottom value=100nF
C244 "Capacitor" C0201_MURATA_GRM033_H0P3 58.6,36.331 r0 bottom value=100nF
C246 "Capacitor" C0201_MURATA_GRM033_H0P3 67.666,34.986 r180 bottom value=100nF
C248 "Capacitor" C0201_MURATA_GRM033_H0P3 58.958,33.002 r0 top value=100nF
C250 "Capacitor" C0201_MURATA_GRM033_H0P3 58.958,33.572 r0 top value=1uF
C251 "Capacitor" C0201_MURATA_GRM033_H0P3 68.165,33.588 r180 bottom value=100nF
CN12 "Header 2x1" CON_MOLEX_53047-0210 47.8,46.475 r180 bottom
D6 "DIODE_3P_DUAL_COMMON_CATHODE" DIO_SOT23 48.773,41.573 r90 bottom value=BAT54CFILM
L2 "Inductor" IND_2016_MURATA_DFE2016 22.388,46.519 r90 top value=0.68uH
L3 "Inductor" IND_2016_MURATA_DFE2016 29.525,46.525 r90 top value=0.68uH
L4 "Inductor" IND_2520_TOKO_DFE252012P 23.926,24.232 r90 top value=2.2uH
L5 "Inductor" IND_2016_MURATA_DFE2016 31.538,41.819 r0 top value=0.68uH
LD11 "LED_green" LED_0603_OSRAM_LG-Q396-PS-35_GREEN_1A2K_H0P4 11.386,35.272 r270 top value=Green
R1 "Resistor" R0201_H0P23 66.751,43.42 r270 bottom value=240R
R2 "Resistor" R0201_H0P23 85.461,34.965 r90 bottom value=240R
R42 "Resistor" R0402 78.986,45.505 r270 bottom value=10K
R52 "Resistor" R0402 23.176,20.257 r0 top value=560R
R56 "Resistor" R0402 16.026,21.232 r270 top value=75K
R57 "Resistor" R0402 17.001,21.232 r90 top value=24K
R64 "Resistor" R0402 53.485,37.575 r180 top value=0R
R66 "Resistor" R0402 48.633,43.917 r180 bottom value=20R
R67 "Resistor" R0402 46.3,40.125 r270 bottom value=0R
R69 "Resistor" R0402 14.693,22.416 r0 top value=0R
R75 "Resistor" R0402 55.959,33.546 r0 top value=0R
R101 "Resistor" R0402 74.375,56.325 r90 bottom value=10K
R103 "Resistor" R0402 80.171,57.511 r90 bottom value=10K
R104 "Resistor" R0402 80.175,55.805 r270 bottom value=10K
R210 "Resistor" R0402 11.386,37.465 r270 top value=270R
R248 "Resistor" R0402 80.657,58.98 r0 bottom value=10K
R260 "Resistor" R0402 20.243,45.444 r180 bottom value=1K5
R261 "Resistor" R0402 20.243,44.469 r180 bottom value=1K5
R267 "Resistor" R0402 57.773,34.723 r180 bottom value=0R
R269 "Resistor" R0402 58.956,31.808 r90 top value=0R
R272 "Resistor" R0402 40.55,31.925 r0 bottom value=10K
TP21 "Test Point" TP_SMD_1MM 78.516,55.665 r90 bottom value=N/A
U1 "IC_STM32MP235FAK3" ICC_VFBGA424_14X14_P050_H1P0_CODE-B0MP 62.875,41.325 r0 top locked value=STM32MP235FAK3
U2 "MT53E1G32D2FW-046 WT:C" ICC_TFBGA200_10X14P5_P080_H1P05_PS0P3 85.26,41.29 r180 top locked
U26 "STPMIC2L" ICC_VFQFPN40-EPAD_5X5_P040 25.488,41.144 r90 top value=STPMIC2LAPQR
U37 "eMMC_THGBMTG5D1LBAIL" ICC_P-WFBGA153_13X11P5_P050 77.675,58.405 r0 top locked value=THGBMTG5D1LBAIL
U54 "ST1S31PUR" ICC_VFDFPN8-EPAD_3X3_P065 19.401,22.082 r270 top
X1 "XTAL_2_PINS" CRY_NX2012SA_2P 51.059,37.225 r270 top value=32.768KHz
X2 "XTAL_4_PINS" CRY_NX1612SA_4P 54.759,32.135 r180 top value=40MHz

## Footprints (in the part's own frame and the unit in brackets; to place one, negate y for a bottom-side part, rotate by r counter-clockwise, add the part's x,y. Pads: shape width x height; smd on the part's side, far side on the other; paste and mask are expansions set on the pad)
C0201_H0P5 [mm] "MCD-01534"
  rect 0.4x0.5 smd mask+0.05: 1(-0.3,0) 2(0.3,0)
  body extent -0.35,-0.2 0.35,0.2, height 0.55
C0201_MURATA_GRM033_H0P3 [mm] "GRM033R60J105ME11"
  rect 0.35x0.35 smd mask+0.05: 1(-0.275,0) 2(0.275,0)
  body extent -0.32,-0.17 0.32,0.17, height 0.33
C0402 [mm]
  rect 0.51x0.56 smd mask+0.05: 1(-0.45,0) 2(0.45,0)
  body extent -0.5,-0.3 0.5,0.3, height 0.4
C0603 [mm]
  rect 0.64x0.89 smd mask+0.05: 1(-0.7,0) 2(0.7,0)
  silkscreen extent -1.05,-0.55 1.02,0.55, body extent -0.9,-0.5 0.9,0.5, height 1.4
CON_MOLEX_53047-0210 [mm]
  oval 1x1.3 hole 0.5 mask+0.05: 1(-0.625,0) 2(0.625,0)
  silkscreen extent -2.12,-1.15 2.13,2.05, body extent -2.12,-1.15 2.13,2.05, height 4.2
CPOL_TCJ-B_1210_H210 [mm] "MCD-01791"
  rect 1.35x2.8 smd mask+0.05: 1(-1.375,0) 2(1.375,0)
  silkscreen extent -2.33,-1.68 1.85,1.68, body extent -1.85,-1.5 1.85,1.5, height 2.11
CRY_NX1612SA_4P [mm] "MCD-02262"
  rect 0.75x0.6 smd mask+0.038: 1(-0.525,-0.375) 2(0.525,-0.375) 3(0.525,0.375) 4(-0.525,0.375)
  silkscreen extent -1.02,-0.8 0.03,0.6, body extent -0.8,-0.6 0.8,0.6, height 0.51
CRY_NX2012SA_2P [mm]
  rect 1x1.25 smd mask+0.05: 1(-0.75,0) 2(0.75,0)
  silkscreen extent -1.05,-0.75 1.05,0.75, body extent -1.05,-0.63 1.05,0.63, height 0.6
DIO_SOT23 [mm]
  rect 1x1.4 smd mask+0.05: 1(-0.95,-1.1) 2(0.95,-1.1) 3(0,1.1)
  silkscreen extent -1.63,-0.82 1.63,0.82, body extent -1.56,-1.25 1.56,1.25, height 1.1
ICC_P-WFBGA153_13X11P5_P050 [mm]
  round 0.23 smd mask+0.05: A1(-3.25,-3.25) A2(-3.25,-2.75) A3(-3.25,-2.25) A4(-3.25,-1.75) A5(-3.25,-1.25) A6(-3.25,-0.75) A7(-3.25,-0.25) A8(-3.25,0.25) A9(-3.25,0.75) A10(-3.25,1.25) A11(-3.25,1.75) A12(-3.25,2.25) A13(-3.25,2.75) A14(-3.25,3.25) B1(-2.75,-3.25) B2(-2.75,-2.75) B3(-2.75,-2.25) B4(-2.75,-1.75) B5(-2.75,-1.25) B6(-2.75,-0.75) B7(-2.75,-0.25) B8(-2.75,0.25) B9(-2.75,0.75) B10(-2.75,1.25) B11(-2.75,1.75) B12(-2.75,2.25) B13(-2.75,2.75) B14(-2.75,3.25) C1(-2.25,-3.25) C2(-2.25,-2.75) C3(-2.25,-2.25) C4(-2.25,-1.75) C5(-2.25,-1.25) C6(-2.25,-0.75) C7(-2.25,-0.25) C8(-2.25,0.25) C9(-2.25,0.75) C10(-2.25,1.25) C11(-2.25,1.75) C12(-2.25,2.25) C13(-2.25,2.75) C14(-2.25,3.25) D1(-1.75,-3.25) D2(-1.75,-2.75) D3(-1.75,-2.25) D4(-1.75,-1.75) D12(-1.75,2.25) D13(-1.75,2.75) D14(-1.75,3.25) E1(-1.25,-3.25) E2(-1.25,-2.75) E3(-1.25,-2.25) E5(-1.25,-1.25) E6(-1.25,-0.75) E7(-1.25,-0.25) E8(-1.25,0.25) E9(-1.25,0.75) E10(-1.25,1.25) E12(-1.25,2.25) E13(-1.25,2.75) E14(-1.25,3.25) F1(-0.75,-3.25) F2(-0.75,-2.75) F3(-0.75,-2.25) F5(-0.75,-1.25) F10(-0.75,1.25) F12(-0.75,2.25) F13(-0.75,2.75) F14(-0.75,3.25) G1(-0.25,-3.25) G2(-0.25,-2.75) G3(-0.25,-2.25) G5(-0.25,-1.25) G10(-0.25,1.25) G12(-0.25,2.25) G13(-0.25,2.75) G14(-0.25,3.25) H1(0.25,-3.25) H2(0.25,-2.75) H3(0.25,-2.25) H5(0.25,-1.25) H10(0.25,1.25) H12(0.25,2.25) H13(0.25,2.75) H14(0.25,3.25) J1(0.75,-3.25) J2(0.75,-2.75) J3(0.75,-2.25) J5(0.75,-1.25) J10(0.75,1.25) J12(0.75,2.25) J13(0.75,2.75) J14(0.75,3.25) K1(1.25,-3.25) K2(1.25,-2.75) K3(1.25,-2.25) K5(1.25,-1.25) K6(1.25,-0.75) K7(1.25,-0.25) K8(1.25,0.25) K9(1.25,0.75) K10(1.25,1.25) K12(1.25,2.25) K13(1.25,2.75) K14(1.25,3.25) L1(1.75,-3.25) L2(1.75,-2.75) L3(1.75,-2.25) L12(1.75,2.25) L13(1.75,2.75) L14(1.75,3.25) M1(2.25,-3.25) M2(2.25,-2.75) M3(2.25,-2.25) M4(2.25,-1.75) M5(2.25,-1.25) M6(2.25,-0.75) M7(2.25,-0.25) M8(2.25,0.25) M9(2.25,0.75) M10(2.25,1.25) M11(2.25,1.75) M12(2.25,2.25) M13(2.25,2.75) M14(2.25,3.25) N1(2.75,-3.25) N2(2.75,-2.75) N3(2.75,-2.25) N4(2.75,-1.75) N5(2.75,-1.25) N6(2.75,-0.75) N7(2.75,-0.25) N8(2.75,0.25) N9(2.75,0.75) N10(2.75,1.25) N11(2.75,1.75) N12(2.75,2.25) N13(2.75,2.75) N14(2.75,3.25) P1(3.25,-3.25) P2(3.25,-2.75) P3(3.25,-2.25) P4(3.25,-1.75) P5(3.25,-1.25) P6(3.25,-0.75) P7(3.25,-0.25) P8(3.25,0.25) P9(3.25,0.75) P10(3.25,1.25) P11(3.25,1.75) P12(3.25,2.25) P13(3.25,2.75) P14(3.25,3.25)
  silkscreen extent -6.78,-6.02 6.63,5.87, body extent -6.55,-5.8 6.55,5.8, height 1
ICC_TFBGA200_10X14P5_P080_H1P05_PS0P3 [mm] "MCD-04012"
  round 0.3 smd mask+0.05: A1(-4.4,6.825) A2(-3.6,6.825) A3(-2.8,6.825) A4(-2,6.825) A5(-1.2,6.825) A8(1.2,6.825) A9(2,6.825) A10(2.8,6.825) A11(3.6,6.825) A12(4.4,6.825) AA1(-4.4,-6.175) AA2(-3.6,-6.175) AA3(-2.8,-6.175) AA4(-2,-6.175) AA5(-1.2,-6.175) AA8(1.2,-6.175) AA9(2,-6.175) AA10(2.8,-6.175) AA11(3.6,-6.175) AA12(4.4,-6.175) AB1(-4.4,-6.825) AB2(-3.6,-6.825) AB3(-2.8,-6.825) AB4(-2,-6.825) AB5(-1.2,-6.825) AB8(1.2,-6.825) AB9(2,-6.825) AB10(2.8,-6.825) AB11(3.6,-6.825) AB12(4.4,-6.825) B1(-4.4,6.175) B2(-3.6,6.175) B3(-2.8,6.175) B4(-2,6.175) B5(-1.2,6.175) B8(1.2,6.175) B9(2,6.175) B10(2.8,6.175) B11(3.6,6.175) B12(4.4,6.175) C1(-4.4,5.525) C2(-3.6,5.525) C3(-2.8,5.525) C4(-2,5.525) C5(-1.2,5.525) C8(1.2,5.525) C9(2,5.525) C10(2.8,5.525) C11(3.6,5.525) C12(4.4,5.525) D1(-4.4,4.875) D2(-3.6,4.875) D3(-2.8,4.875) D4(-2,4.875) D5(-1.2,4.875) D8(1.2,4.875) D9(2,4.875) D10(2.8,4.875) D11(3.6,4.875) D12(4.4,4.875) E1(-4.4,4.225) E2(-3.6,4.225) E3(-2.8,4.225) E4(-2,4.225) E5(-1.2,4.225) E8(1.2,4.225) E9(2,4.225) E10(2.8,4.225) E11(3.6,4.225) E12(4.4,4.225) F1(-4.4,3.575) F2(-3.6,3.575) F3(-2.8,3.575) F4(-2,3.575) F5(-1.2,3.575) F8(1.2,3.575) F9(2,3.575) F10(2.8,3.575) F11(3.6,3.575) F12(4.4,3.575) G1(-4.4,2.925) G2(-3.6,2.925) G3(-2.8,2.925) G4(-2,2.925) G5(-1.2,2.925) G8(1.2,2.925) G9(2,2.925) G10(2.8,2.925) G11(3.6,2.925) G12(4.4,2.925) H1(-4.4,2.275) H2(-3.6,2.275) H3(-2.8,2.275) H4(-2,2.275) H5(-1.2,2.275) H8(1.2,2.275) H9(2,2.275) H10(2.8,2.275) H11(3.6,2.275) H12(4.4,2.275) J1(-4.4,1.625) J2(-3.6,1.625) J3(-2.8,1.625) J4(-2,1.625) J5(-1.2,1.625) J8(1.2,1.625) J9(2,1.625) J10(2.8,1.625) J11(3.6,1.625) J12(4.4,1.625) K1(-4.4,0.975) K2(-3.6,0.975) K3(-2.8,0.975) K4(-2,0.975) K5(-1.2,0.975) K8(1.2,0.975) K9(2,0.975) K10(2.8,0.975) K11(3.6,0.975) K12(4.4,0.975) N1(-4.4,-0.975) N2(-3.6,-0.975) N3(-2.8,-0.975) N4(-2,-0.975) N5(-1.2,-0.975) N8(1.2,-0.975) N9(2,-0.975) N10(2.8,-0.975) N11(3.6,-0.975) N12(4.4,-0.975) P1(-4.4,-1.625) P2(-3.6,-1.625) P3(-2.8,-1.625) P4(-2,-1.625) P5(-1.2,-1.625) P8(1.2,-1.625) P9(2,-1.625) P10(2.8,-1.625) P11(3.6,-1.625) P12(4.4,-1.625) R1(-4.4,-2.275) R2(-3.6,-2.275) R3(-2.8,-2.275) R4(-2,-2.275) R5(-1.2,-2.275) R8(1.2,-2.275) R9(2,-2.275) R10(2.8,-2.275) R11(3.6,-2.275) R12(4.4,-2.275) T1(-4.4,-2.925) T2(-3.6,-2.925) T3(-2.8,-2.925) T4(-2,-2.925) T5(-1.2,-2.925) T8(1.2,-2.925) T9(2,-2.925) T10(2.8,-2.925) T11(3.6,-2.925) T12(4.4,-2.925) U1(-4.4,-3.575) U2(-3.6,-3.575) U3(-2.8,-3.575) U4(-2,-3.575) U5(-1.2,-3.575) U8(1.2,-3.575) U9(2,-3.575) U10(2.8,-3.575) U11(3.6,-3.575) U12(4.4,-3.575) V1(-4.4,-4.225) V2(-3.6,-4.225) V3(-2.8,-4.225) V4(-2,-4.225) V5(-1.2,-4.225) V8(1.2,-4.225) V9(2,-4.225) V10(2.8,-4.225) V11(3.6,-4.225) V12(4.4,-4.225) W1(-4.4,-4.875) W2(-3.6,-4.875) W3(-2.8,-4.875) W4(-2,-4.875) W5(-1.2,-4.875) W8(1.2,-4.875) W9(2,-4.875) W10(2.8,-4.875) W11(3.6,-4.875) W12(4.4,-4.875) Y1(-4.4,-5.525) Y2(-3.6,-5.525) Y3(-2.8,-5.525) Y4(-2,-5.525) Y5(-1.2,-5.525) Y8(1.2,-5.525) Y9(2,-5.525) Y10(2.8,-5.525) Y11(3.6,-5.525) Y12(4.4,-5.525)
  silkscreen extent -5.2,-7.3 5.05,7.45, body extent -5.05,-7.3 5.05,7.3, height 1.06
ICC_VFBGA424_14X14_P050_H1P0_CODE-B0MP [mm] "MCD_05079"
  round 0.23 smd paste+0.025 mask+0.05: 1A1(-2.75,2.75) 1A3(-1.75,2.75) 1A5(-0.75,2.75) 1A7(0.25,2.75) 1A9(1.25,2.75) 1A11(2.25,2.75) 1B2(-2.25,2.25) 1B4(-1.25,2.25) 1B6(-0.25,2.25) 1B8(0.75,2.25) 1B10(1.75,2.25) 1B12(2.75,2.25) 1C1(-2.75,1.75) 1C3(-1.75,1.75) 1C5(-0.75,1.75) 1C7(0.25,1.75) 1C9(1.25,1.75) 1C11(2.25,1.75) 1D2(-2.25,1.25) 1D4(-1.25,1.25) 1D6(-0.25,1.25) 1D8(0.75,1.25) 1D10(1.75,1.25) 1D12(2.75,1.25) 1E1(-2.75,0.75) 1E3(-1.75,0.75) 1E5(-0.75,0.75) 1E7(0.25,0.75) 1E9(1.25,0.75) 1E11(2.25,0.75) 1F2(-2.25,0.25) 1F4(-1.25,0.25) 1F6(-0.25,0.25) 1F8(0.75,0.25) 1F10(1.75,0.25) 1F12(2.75,0.25) 1G1(-2.75,-0.25) 1G3(-1.75,-0.25) 1G5(-0.75,-0.25) 1G7(0.25,-0.25) 1G9(1.25,-0.25) 1G11(2.25,-0.25) 1H2(-2.25,-0.75) 1H4(-1.25,-0.75) 1H6(-0.25,-0.75) 1H8(0.75,-0.75) 1H10(1.75,-0.75) 1H12(2.75,-0.75) 1J1(-2.75,-1.25) 1J3(-1.75,-1.25) 1J5(-0.75,-1.25) 1J7(0.25,-1.25) 1J9(1.25,-1.25) 1J11(2.25,-1.25) 1K2(-2.25,-1.75) 1K4(-1.25,-1.75) 1K6(-0.25,-1.75) 1K8(0.75,-1.75) 1K10(1.75,-1.75) 1K12(2.75,-1.75) 1L1(-2.75,-2.25) 1L3(-1.75,-2.25) 1L5(-0.75,-2.25) 1L7(0.25,-2.25) 1L9(1.25,-2.25) 1L11(2.25,-2.25) 1M2(-2.25,-2.75) 1M4(-1.25,-2.75) 1M6(-0.25,-2.75) 1M8(0.75,-2.75) 1M10(1.75,-2.75) 1M12(2.75,-2.75) A1(-6.5,6.5) A2(-6,6.5) A3(-5.5,6.5) A6(-4,6.5) A7(-3.5,6.5) A10(-2,6.5) A11(-1.5,6.5) A14(0,6.5) A15(0.5,6.5) A18(2,6.5) A19(2.5,6.5) A22(4,6.5) A23(4.5,6.5) A26(6,6.5) A27(6.5,6.5) AA1(-6.5,-3.5) AA2(-6,-3.5) AA3(-5.5,-3.5) AA5(-4.5,-3.5) AA7(-3.5,-3.5) AA9(-2.5,-3.5) AA11(-1.5,-3.5) AA13(-0.5,-3.5) AA15(0.5,-3.5) AA17(1.5,-3.5) AA19(2.5,-3.5) AA21(3.5,-3.5) AA23(4.5,-3.5) AA25(5.5,-3.5) AA26(6,-3.5) AB1(-6.5,-4) AB2(-6,-4) AB3(-5.5,-4) AB4(-5,-4) AB6(-4,-4) AB8(-3,-4) AB10(-2,-4) AB12(-1,-4) AB14(0,-4) AB16(1,-4) AB18(2,-4) AB20(3,-4) AB22(4,-4) AB24(5,-4) AB25(5.5,-4) AB26(6,-4) AB27(6.5,-4) AC2(-6,-4.5) AC3(-5.5,-4.5) AC5(-4.5,-4.5) AC7(-3.5,-4.5) AC9(-2.5,-4.5) AC11(-1.5,-4.5) AC13(-0.5,-4.5) AC15(0.5,-4.5) AC17(1.5,-4.5) AC19(2.5,-4.5) AC21(3.5,-4.5) AC23(4.5,-4.5) AC25(5.5,-4.5) AC26(6,-4.5) AC27(6.5,-4.5) AD3(-5.5,-5) AD4(-5,-5) AD6(-4,-5) AD8(-3,-5) AD10(-2,-5) AD12(-1,-5) AD14(0,-5) AD16(1,-5) AD18(2,-5) AD20(3,-5) AD22(4,-5) AD24(5,-5) AD25(5.5,-5) AE1(-6.5,-5.5) AE2(-6,-5.5) AE3(-5.5,-5.5) AE4(-5,-5.5) AE5(-4.5,-5.5) AE6(-4,-5.5) AE7(-3.5,-5.5) AE8(-3,-5.5) AE9(-2.5,-5.5) AE10(-2,-5.5) AE11(-1.5,-5.5) AE12(-1,-5.5) AE13(-0.5,-5.5) AE14(0,-5.5) AE15(0.5,-5.5) AE16(1,-5.5) AE17(1.5,-5.5) AE18(2,-5.5) AE19(2.5,-5.5) AE20(3,-5.5) AE21(3.5,-5.5) AE22(4,-5.5) AE23(4.5,-5.5) AE24(5,-5.5) AE25(5.5,-5.5) AE26(6,-5.5) AF1(-6.5,-6) AF2(-6,-6) AF3(-5.5,-6) AF5(-4.5,-6) AF6(-4,-6) AF7(-3.5,-6) AF9(-2.5,-6) AF10(-2,-6) AF11(-1.5,-6) AF13(-0.5,-6) AF14(0,-6) AF15(0.5,-6) AF17(1.5,-6) AF18(2,-6) AF19(2.5,-6) AF21(3.5,-6) AF22(4,-6) AF23(4.5,-6) AF25(5.5,-6) AF26(6,-6) AF27(6.5,-6) AG1(-6.5,-6.5) AG2(-6,-6.5) AG5(-4.5,-6.5) AG6(-4,-6.5) AG9(-2.5,-6.5) AG10(-2,-6.5) AG13(-0.5,-6.5) AG14(0,-6.5) AG17(1.5,-6.5) AG18(2,-6.5) AG21(3.5,-6.5) AG22(4,-6.5) AG25(5.5,-6.5) AG26(6,-6.5) AG27(6.5,-6.5) B1(-6.5,6) B2(-6,6) B3(-5.5,6) B5(-4.5,6) B6(-4,6) B7(-3.5,6) B9(-2.5,6) B10(-2,6) B11(-1.5,6) B13(-0.5,6) B14(0,6) B15(0.5,6) B17(1.5,6) B18(2,6) B19(2.5,6) B21(3.5,6) B22(4,6) B23(4.5,6) B25(5.5,6) B26(6,6) B27(6.5,6) C2(-6,5.5) C3(-5.5,5.5) C4(-5,5.5) C5(-4.5,5.5) C6(-4,5.5) C7(-3.5,5.5) C8(-3,5.5) C9(-2.5,5.5) C10(-2,5.5) C11(-1.5,5.5) C12(-1,5.5) C13(-0.5,5.5) C14(0,5.5) C15(0.5,5.5) C16(1,5.5) C17(1.5,5.5) C18(2,5.5) C19(2.5,5.5) C20(3,5.5) C21(3.5,5.5) C22(4,5.5) C23(4.5,5.5) C24(5,5.5) C25(5.5,5.5) C26(6,5.5) C27(6.5,5.5) D3(-5.5,5) D4(-5,5) D6(-4,5) D8(-3,5) D10(-2,5) D12(-1,5) D14(0,5) D16(1,5) D18(2,5) D20(3,5) D22(4,5) D24(5,5) D25(5.5,5) E1(-6.5,4.5) E2(-6,4.5) E3(-5.5,4.5) E5(-4.5,4.5) E7(-3.5,4.5) E9(-2.5,4.5) E11(-1.5,4.5) E13(-0.5,4.5) E15(0.5,4.5) E17(1.5,4.5) E19(2.5,4.5) E21(3.5,4.5) E23(4.5,4.5) E25(5.5,4.5) E26(6,4.5) F1(-6.5,4) F2(-6,4) F3(-5.5,4) F4(-5,4) F6(-4,4) F8(-3,4) F10(-2,4) F12(-1,4) F14(0,4) F16(1,4) F18(2,4) F20(3,4) F22(4,4) F24(5,4) F25(5.5,4) F26(6,4) F27(6.5,4) G2(-6,3.5) G3(-5.5,3.5) G5(-4.5,3.5) G7(-3.5,3.5) G9(-2.5,3.5) G11(-1.5,3.5) G13(-0.5,3.5) G15(0.5,3.5) G17(1.5,3.5) G19(2.5,3.5) G21(3.5,3.5) G23(4.5,3.5) G25(5.5,3.5) G26(6,3.5) G27(6.5,3.5) H3(-5.5,3) H4(-5,3) H6(-4,3) H22(4,3) H24(5,3) H25(5.5,3) J1(-6.5,2.5) J2(-6,2.5) J3(-5.5,2.5) J5(-4.5,2.5) J7(-3.5,2.5) J21(3.5,2.5) J23(4.5,2.5) J25(5.5,2.5) J26(6,2.5) K1(-6.5,2) K2(-6,2) K3(-5.5,2) K4(-5,2) K6(-4,2) K22(4,2) K24(5,2) K25(5.5,2) K26(6,2) K27(6.5,2) L2(-6,1.5) L3(-5.5,1.5) L5(-4.5,1.5) L7(-3.5,1.5) L21(3.5,1.5) L23(4.5,1.5) L25(5.5,1.5) L26(6,1.5) L27(6.5,1.5) M3(-5.5,1) M4(-5,1) M6(-4,1) M22(4,1) M24(5,1) M25(5.5,1) N1(-6.5,0.5) N2(-6,0.5) N3(-5.5,0.5) N5(-4.5,0.5) N7(-3.5,0.5) N21(3.5,0.5) N23(4.5,0.5) N25(5.5,0.5) N26(6,0.5) P1(-6.5,0) P2(-6,0) P3(-5.5,0) P4(-5,0) P6(-4,0) P22(4,0) P24(5,0) P25(5.5,0) P26(6,0) P27(6.5,0) R2(-6,-0.5) R3(-5.5,-0.5) R5(-4.5,-0.5) R7(-3.5,-0.5) R21(3.5,-0.5) R23(4.5,-0.5) R25(5.5,-0.5) R26(6,-0.5) R27(6.5,-0.5) T3(-5.5,-1) T4(-5,-1) T6(-4,-1) T22(4,-1) T24(5,-1) T25(5.5,-1) U1(-6.5,-1.5) U2(-6,-1.5) U3(-5.5,-1.5) U5(-4.5,-1.5) U7(-3.5,-1.5) U21(3.5,-1.5) U23(4.5,-1.5) U25(5.5,-1.5) U26(6,-1.5) V1(-6.5,-2) V2(-6,-2) V3(-5.5,-2) V4(-5,-2) V6(-4,-2) V22(4,-2) V24(5,-2) V25(5.5,-2) V26(6,-2) V27(6.5,-2) W2(-6,-2.5) W3(-5.5,-2.5) W5(-4.5,-2.5) W7(-3.5,-2.5) W21(3.5,-2.5) W23(4.5,-2.5) W25(5.5,-2.5) W26(6,-2.5) W27(6.5,-2.5) Y3(-5.5,-3) Y4(-5,-3) Y6(-4,-3) Y22(4,-3) Y24(5,-3) Y25(5.5,-3)
  silkscreen extent -7.17,-7 7,7.17, body extent -7,-7 7,7, height 1.21
ICC_VFDFPN8-EPAD_3X3_P065 [mm] "MCD-02243"
  round 0.025 smd mask+0.05: 1(-0.975,-1.475) 2(-0.325,-1.475) 3(0.325,-1.475) 4(0.975,-1.475) 5(0.975,1.475) 6(0.325,1.475) 7(-0.325,1.475) 8(-0.975,1.475)
  rect 2.55x1.65 smd mask+0.05: 9(0,0)
  Top Layer region: -0.15,1.2 -0.163,1.133 -0.201,1.076 -0.258,1.038 -0.325,1.025 -0.325,1.025 -0.392,1.038 -0.449,1.076 -0.487,1.133 -0.5,1.2 -0.5,1.2 -0.5,1.75 -0.15,1.75
  Top Layer region: 1.15,-1.2 1.137,-1.133 1.099,-1.076 1.042,-1.038 0.975,-1.025 0.975,-1.025 0.908,-1.038 0.852,-1.076 0.814,-1.132 0.801,-1.199 0.801,-1.199 0.801,-1.2 0.8,-1.2 0.8,-1.75 1.15,-1.75
  Top Layer region: -0.8,1.2 -0.813,1.133 -0.851,1.076 -0.908,1.038 -0.975,1.025 -0.975,1.025 -0.975,1.025 -1.042,1.038 -1.099,1.076 -1.137,1.133 -1.15,1.2 -1.15,1.2 -1.15,1.75 -0.8,1.75
  Top Layer region: 0.5,1.2 0.487,1.133 0.449,1.076 0.392,1.038 0.325,1.025 0.325,1.025 0.325,1.025 0.258,1.038 0.201,1.076 0.163,1.133 0.15,1.2 0.15,1.2 0.15,1.2 0.15,1.75 0.5,1.75
  Top Layer region: 1.15,1.2 1.137,1.133 1.099,1.076 1.042,1.038 0.975,1.025 0.975,1.025 0.975,1.025 0.908,1.038 0.851,1.076 0.813,1.133 0.8,1.2 0.8,1.2 0.8,1.75 1.15,1.75
  Top Layer region: 0.5,-1.2 0.487,-1.133 0.449,-1.076 0.392,-1.038 0.325,-1.025 0.325,-1.025 0.325,-1.025 0.258,-1.038 0.201,-1.076 0.163,-1.133 0.15,-1.2 0.15,-1.2 0.15,-1.75 0.5,-1.75
  Top Layer region: -0.15,-1.2 -0.163,-1.133 -0.201,-1.076 -0.258,-1.038 -0.325,-1.025 -0.325,-1.025 -0.325,-1.025 -0.392,-1.038 -0.449,-1.076 -0.487,-1.133 -0.5,-1.2 -0.5,-1.2 -0.5,-1.75 -0.15,-1.75
  Top Layer region: -0.8,-1.2 -0.813,-1.133 -0.851,-1.076 -0.908,-1.038 -0.975,-1.025 -0.975,-1.025 -0.975,-1.025 -1.042,-1.038 -1.099,-1.076 -1.137,-1.133 -1.15,-1.2 -1.15,-1.2 -1.15,-1.75 -0.8,-1.75
  silkscreen extent -1.5,-1.5 1.5,1.5, body extent -1.5,-1.5 1.5,1.5, height 1
ICC_VFQFPN40-EPAD_5X5_P040 [mm] "MCD-04051"
  rect 0.2x0.75 smd mask+0.05: 1(-1.8,-2.475) 10(1.8,-2.475) 21(1.8,2.475) 30(-1.8,2.475)
  rect 0.2x0.8 smd mask+0.05: 2(-1.4,-2.45) 3(-1,-2.45) 4(-0.6,-2.45) 5(-0.2,-2.45) 6(0.2,-2.45) 7(0.6,-2.45) 8(1,-2.45) 9(1.4,-2.45) 22(1.4,2.45) 23(1,2.45) 24(0.6,2.45) 25(0.2,2.45) 26(-0.2,2.45) 27(-0.6,2.45) 28(-1,2.45) 29(-1.4,2.45)
  rect 0.75x0.2 smd mask+0.05: 11(2.475,-1.8) 20(2.475,1.8) 31(-2.475,1.8) 40(-2.475,-1.8)
  rect 0.8x0.2 smd mask+0.05: 12(2.45,-1.4) 13(2.45,-1) 14(2.45,-0.6) 15(2.45,-0.2) 16(2.45,0.2) 17(2.45,0.6) 18(2.45,1) 19(2.45,1.4) 32(-2.45,1.4) 33(-2.45,1) 34(-2.45,0.6) 35(-2.45,0.2) 36(-2.45,-0.2) 37(-2.45,-0.6) 38(-2.45,-1) 39(-2.45,-1.4)
  rect 3.65x3.65 smd mask+0.05: 41(0,0)
  silkscreen extent -2.63,-2.63 2.63,2.63, body extent -2.5,-2.5 2.5,2.5, height 0.9
IND_2016_MURATA_DFE2016 [mm] "MCD-03141"
  rect 0.8x1.8 smd mask+0.05: 1(-0.8,0) 2(0.8,0)
  silkscreen extent -0.28,-0.87 0.28,0.87, body extent -1.07,-0.87 1.08,0.87, height 1
IND_2520_TOKO_DFE252012P [mm]
  rect 0.8x2 smd mask+0.05: 1(-1,0) 2(1,0)
  silkscreen extent -1.35,-1.12 1.35,1.12, body extent -1.35,-1.1 1.35,1.1, height 2
LED_0603_OSRAM_LG-Q396-PS-35_GREEN_1A2K_H0P4 [mm]
  rect 0.8x0.8 smd mask+0.05: 1(-0.75,0) 2(0.75,0)
  silkscreen extent -0.85,-0.53 1.28,0.53, body extent -0.85,-0.45 0.85,0.45, height 0.6
R0201_H0P23 [mm] "MCD-00702"
  rect 0.4x0.5 smd mask+0.05: 1(-0.3,0) 2(0.3,0)
  body extent -0.32,-0.17 0.32,0.17, height 0.26
R0402 [mm]
  rect 0.51x0.7 smd mask+0.05: 1(-0.45,0) 2(0.45,0)
  body extent -0.52,-0.3 0.52,0.3, height 0.4
SWI_WE_434121025816 [mm] "MCD-03492"
  rect 1.5x1.4 smd: 1(-3.25,0) 2(3.25,0)
  silkscreen extent -3,-1.95 3,1.95, body extent -3.65,-1.95 3.65,1.95, height 2.51
TP_SMD_1MM [mm]
  round 1 smd paste-10 mask+0.05: 1(0,0)
  silkscreen extent -0.7,-0.7 0.7,0.7

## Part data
B2: library part MCD-03492, "Switch tactile, SPST-NO, 12V, 50mA, 3x2.6mm", Manufacturer="WURTH ELEKTRONIK", Manufacturer_Part_Number=434121025816, Package=6x3.8mm
C2 C3 C10 C11: library part MCD-01341, "Capacitor, MLCC, 10uF, 6V3, X5R, 20%, 0603, T=0.8mm", Manufacturer=MURATA, Manufacturer_Part_Number=GRM188R60J106ME47, Package=0603
C4 C5 C6 C7 C8 C9 C12 C13 C14 C15 C16 C17 C18 C19 C20 C21 C87 C118 C130: library part MCD-00006, "Capacitor, MLCC, 100nF, 16V, X7R, +/-10%, 0402, T=0.5mm", Manufacturer=YAGEO, Manufacturer_Part_Number=CC0402KRX7R7BB104, Package=0402
C22 C23 C24 C26 C27 C28 C34 C35 C36 C41 C183 C200 C202: library part MCD-00100, "Capacitor, MLCC, 22uF, 6V3, X5R, +/-20%, 0603, T=0.8mm", Manufacturer=MURATA, Manufacturer_Part_Number=GRM188R60J226MEA0, Package=0603
C29 C32 C38 C214: library part MCD-00099, "Capacitor, MLCC, 10uF, 10V, X5R, +/-10%, 0603, T=0.8mm", Manufacturer=MURATA, Manufacturer_Part_Number=GRM188R61A106KE69, Package=0603
C33: library part MCD-00011, "Capacitor, MLCC, 10nF, 16V, X7R, +/-10%, 0402, T=0.5mm", Manufacturer=YAGEO, Manufacturer_Part_Number=CC0402KRX7R7BB103, Package=0402
C39 C56 C123 C213: library part MCD-00095, "Capacitor, MLCC, 1uF, 25V, X5R, 10%, 0402, T=0.5mm", Manufacturer=MURATA, Manufacturer_Part_Number=GRM155R61E105KA12, Package=0402
C40 C61 C185 C189 C190 C193 C208 C209 C215: library part MCD-01356, "Capacitor, MLCC, 4.7uF, 6V3, X5R, 20%, 0402, T=0.5mm", Manufacturer=MURATA, Manufacturer_Part_Number=GRM155R60J475ME47, Package=0402
C42 C147: library part MCD-01796, "Capacitor, Tantalum, 100uF, 6V3, 40mR, +/-20%,  Type_B (3528 metric), T=1.9mm", Manufacturer="KYOCERA AVX", Manufacturer_Part_Number=TCJB107M006R0040E, Package="3528 (metric)"
C44 C45 C46 C47 C48 C49 C50 C51 C52 C53 C54 C55 C57 C58 C59 C60 C62 C63 C64 C65 C66 C67 C68 C69 C70 C71 C72 C73 C74 C75 C76 C77 C82 C83 C250: library part MCD-02377, "Capacitor, MLCC, 1uF, 6.3V, X5R, +/-20%, 0201, T=0,3mm", Manufacturer=MURATA, Manufacturer_Part_Number=GRM033R60J105MEA2, Package=0201
C81 C86 C90 C92: library part MCD-00674, "Capacitor, MLCC, 6.8pF, 50V, C0G/NP0, +/-0.25pF, 0402, T=0.5mm", Manufacturer=YAGEO, Manufacturer_Part_Number=CC0402CRNPO9BN6R8, Package=0402
C88: library part MCD-01823, "Capacitor, MLCC, 2.2uF, 6V3, X5R, +/-10%, 0402, T=0.5mm", Manufacturer=MURATA, Manufacturer_Part_Number=GRM155R60J225KE95, Package=0402
C117 C128 C148: library part MCD-02606, "Capacitor, MLCC, 2.2uF, 6.3V, X5R, +/-10%, 0402, T=0.5mm", Manufacturer=YAGEO, Manufacturer_Part_Number=CC0402KRX5R5BB225, Package=0402
C192 C195 C196 C197 C201 C205 C220 C234 C236 C237 C238 C239 C240 C244 C246 C248 C251: library part MCD-01535, "Capacitor, MLCC,100nF, 10V, C0G/NP0, +/-10%, 0201, T=0.3mm", Manufacturer=MURATA, Manufacturer_Part_Number=GRM033R61A104KE15, Package=0201
C219: library part MCD-02198, "Capacitor, MLCC, 10nF, 50V, X7R, +/-10%, 0402, T=0.5mm", Manufacturer=YAGEO, Manufacturer_Part_Number=CC0402KRX7R9BB103, Package=0402
C225: library part MCD-01534, "Capacitor, MLCC, 4,7uF, 6V3, X5R, +/-20%, 0201, T=0.5mm", Manufacturer=MURATA, Manufacturer_Part_Number=GRM035R60J475ME15, Package=0201
C235: library part MCD-02235, "Capacitor, MLCC, 2.2uF, 10V, X5R,+/-10%, 0201, T=0.5mm", Manufacturer=MURATA, Manufacturer_Part_Number=GRM033R61A225KE47, Package=0201
CN12: library part MCD-00655, "Header, 2x1, 1.25mm, VR, TH, T=2.25mm/2.3mm", Manufacturer=MOLEX, Manufacturer_Part_Number=53047-0210
D6: library part MCD-03280, "Diode, Schottky, Dual Common Cathode, 0V3, 300mA, 40V, SOT-23", Manufacturer=STMICROELECTRONICS, Manufacturer_Part_Number=BAT54CFILM, Package=SOT-23
L2 L3 L5: library part MCD-03141, "Inductor, 0.68uH, +/-20%, Itemp= 3100mA, Isat= 4300mA, 0R043, 0806, T=1mm", Manufacturer=MURATA, Manufacturer_Part_Number=DFE201610E-R68M{}P2, Package=0806
L4: library part MCD-00161, "Inductor, 2.2uH, +/-20%, 2,2A, 84mR, 1008, T=1.2mm", Manufacturer=TOKO, Manufacturer_Part_Number=DFE252012P-2R2M{}P2, Package=1008
LD11: library part MCD-00588, "LED, Green, 2V, 20mA, 0603", Manufacturer="AMS OSRAM", Manufacturer_Part_Number="LG Q396-PS-35-0-20-R18", Package=0603
R1 R2: library part MCD-02253, "Resistor, 240R, 0201, +/-1%, 1/20W", Manufacturer=YAGEO, Manufacturer_Part_Number=RC0201FR-07240RL, Package=0201
R42 R101 R103 R104 R248 R272: library part MCD-00053, "Resistor, 10K, 0402, +/-1%, 1/16W", Manufacturer=YAGEO, Manufacturer_Part_Number=RC0402FR-0710KL, Package=0402
R52: library part MCD-00489, "Resistor, 560R, 0402, +/-1%, 1/16W", Manufacturer=YAGEO, Manufacturer_Part_Number=RC0402FR-07560RL, Package=0402
R56: library part MCD-00521, "Resistor, 75K, 0402, +/-1%, 1/16W", Manufacturer=YAGEO, Manufacturer_Part_Number=RC0402FR-0775KL, Package=0402
R57: library part MCD-00435, "Resistor, 24K, 0402, +/-1%, 1/16W", Manufacturer=YAGEO, Manufacturer_Part_Number=RC0402FR-0724KL, Package=0402
R64 R67 R69 R75 R267 R269: library part MCD-00052, "Resistor, 0R, 0402, +/-5%, 1/16W", Manufacturer=YAGEO, Manufacturer_Part_Number=RC0402JR-070RL, Package=0402
R66: library part MCD-00058, "Resistor, 20R, 0402, +/-1%, 1/16W", Manufacturer=YAGEO, Manufacturer_Part_Number=RC0402FR-0720RL, Package=0402
R210: library part MCD-00441, "Resistor, 270R, 0402, +/-1%, 1/16W", Manufacturer=YAGEO, Manufacturer_Part_Number=RC0402FR-07270RL, Package=0402
R260 R261: library part MCD-00068, "Resistor, 1K5, 0402, +/-1%, 1/16W", Manufacturer=YAGEO, Manufacturer_Part_Number=RC0402FR-071K5L, Package=0402
TP21: library part MCD-00074, "Test Point, SMD, 1mm", Manufacturer=N/A, Manufacturer_HQ_COO=Unknown
U1: library part MCD-05079, "MPU, dual core ARM cortex-A35 64-bit + M33 32-bit, 776KB SRAM, With Crypto", Manufacturer=STMICROELECTRONICS, Manufacturer_Part_Number=STM32MP235FAK3, Package=VFBGA424
U2: library part MCD-04160, "Memory, LPDDR4 SDRAM,1V8, 32Gbit, 2133MHz", Manufacturer=MICRON, Package=TFBGA-200
U26: library part MCD-04051, "Power Management IC for STM32MP2x series with 3 step-down SMPS, 7 LDOs, 5 GPOs, VFQFPN40L (5.0 x 5.0 x 1.0 mm)", Manufacturer=STMICROELECTRONICS, Manufacturer_Part_Number=STPMIC2LAPQR, Package="VFQFPN-40 5x5mm"
U37: library part MCD-02799, "Memory, eMMC, 3V3, 4Gbit, 52MHz", Manufacturer=KIOXIA, Manufacturer_Part_Number=THGBMTG5D1LBAIL, Package=WFBGA153
U54: library part MCD-02243, "Regulator, 3A, DC step-down switching", Manufacturer=STMICROELECTRONICS, Manufacturer_HQ_COO=EU, Package=VFDFPN-8
X1: library part MCD-01479, "Crystal, 32.768kHz, 6pF, +/-20ppm, 80K, 2.05x1.2mm", Manufacturer=NDK, Manufacturer_Part_Number=NX2012SA-32.768KHz-EXS00A-MU00527, Package=2.05x1.2mm
X2: library part MCD-02344, "Crystal, 40MHz, 6pF, +/-20ppm, 80R, 1.6x1.2mm", Manufacturer=NDK, Manufacturer_Part_Number=NX1612SA-40MHz-EXS00A-CS13836, Package=1.6x1.2mm

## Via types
v1: diameter 0.55, hole 0.35, Top Layer to Bottom Layer, 364 vias
v2: diameter 0.4, hole 0.2, Top Layer to Bottom Layer, tented both sides, 223 vias
v3: diameter 0.4, hole 0.2, Top Layer to Bottom Layer, 105 vias

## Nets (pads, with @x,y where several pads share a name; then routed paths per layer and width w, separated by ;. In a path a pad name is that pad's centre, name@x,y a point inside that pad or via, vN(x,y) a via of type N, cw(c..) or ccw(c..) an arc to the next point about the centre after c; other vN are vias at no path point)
1V8: C118.2 C128.2 C193.1 C220.2 C236.2 C237.2 C238.2 C239.2 C240.2 C246.2 R101.2 R103.2 R104.2 R248.2 R267.2 R269.1 U1.1E1 U1.AD22 U1.AE23 U1.D18 U1.E17 U1.F20 U1.G5 U1.G7 U1.G9 U1.G19 U1.H6 U26.37 U37.C6 U37.M4 U37.N4 U37.P3 U37.P5 | length 147.5
  Top Layer w0.1: v2(52.882,33.63) 52.882,33.645 53.122,33.885 53.122,33.956 53.244,34.078 53.813,34.078 54.103,34.368 54.86,34.368 54.967,34.474 55.127,34.474 v2(55.146,34.494)
  Top Layer w0.15: U1.G5@58.375,44.825 v2(58.375,44.325) U1.H6@58.875,44.325 ; U1.1E1@60.125,42.075 60.125,42.097 60.085,42.137 60.085,42.17 59.835,42.42 59.835,43.035 59.702,43.168 59.702,43.926 59.304,44.325 U1.H6@58.875,44.325 ; v2@60.792,44.887 v2(60.79,44.885) 60.73,44.825 U1.G9@60.375,44.825 U1.G7@59.375,44.825 U1.H6@58.875,44.325 ; U1.E17@64.375,45.825 64.375,45.828 64.5,45.953 64.5,46.139 64.683,46.322 U1.D18@64.872,46.322 ; U1.D18@64.853,46.325 U1.D18@64.875,46.325 65.372,46.325 v2(65.378,46.319) ; U1.G19@65.378,44.822 65.735,44.465 v2(65.735,44.426) 65.735,44.412 65.973,44.651 65.973,45.205 65.875,45.303 U1.F20@65.875,45.325 ; U1.AD22@66.875,36.325 v2(67.375,36.325) U1.AE23@67.375,35.825 ; U37.P3@80.925,56.155 v2(81.325,56.155)
  Top Layer w0.2: 26.088,37.669 U26.37@26.088,38.694 ; U37.C6@75.425,57.655 75.602,57.832 75.877,57.832 v1(75.925,57.88) ; U37.M4@79.925,56.655 U37.N4@80.425,56.655 ; U37.P3@80.925,56.155 U37.N4@80.425,56.655 ; U37.P5@80.925,57.155 U37.N4@80.425,56.655
  Top Layer w0.3: 26.088,37.669 27.052,36.705 27.052,36.55 27.058,36.544 27.058,36.374 27.143,36.289 C193.1@27.163,36.289 ; C193.1@27.033,36.289 27.033,36.237 26.983,36.187 26.705,36.187 26.438,35.92 26.438,34.21 26.826,33.822 v1@30.55,33.822 ; v2(58.956,30.75) R269.1@58.956,31.358
  Signal Layer 2 w0.2: v2(65.378,46.319) 65.378,45.999 65.794,45.583 65.794,44.612 65.773,44.591 65.773,44.452 v2@65.674,44.353 ; v2@65.734,44.411 65.375,44.053 65.375,43.231 65.284,43.14 65.284,42.894 65.44,42.738 65.44,42.381 65.3,42.241 65.3,41.875 65.406,41.769 65.406,40.806 65.64,40.572 65.694,40.572 65.93,40.336 65.93,39.851 65.35,39.271 65.35,38.834 65.569,38.615 65.569,37.527 65.566,37.525 66.77,36.322 v2@67.372,36.322
  Signal Layer 2 w0.3: v2(58.956,30.75) 58.956,33.296 58.956,33.299 ; 59.631,46.794 60.561,46.794 60.825,46.53 60.825,45.164 60.809,45.148 60.809,44.931 v2@60.79,44.912
  Signal Layer 2 w0.4: 27.333,60.042 27.9,59.475 ; 28.4,59.975 27.9,59.475 ; 59.631,46.794 51.65,54.775 28.8,54.775 27.9,55.675 27.9,59.475
  Signal Layer 2 w0.5: v2(65.378,46.319) 65.7,46.641 65.7,50.475
  Signal Layer 2 w0.6: v1@30.55,33.833 47.874,33.833 48.527,33.18 51.89,33.18 52.363,33.653 52.86,33.653 v2(52.882,33.63) 58.568,33.63 58.929,33.269 58.956,33.296 59.874,34.214 66.696,34.214 67.375,34.893 v2(67.375,36.325)
  Bottom Layer w0.2: C239.2@64.4,46.837 64.86,46.837 v2(65.378,46.319) ; v2@65.735,44.411 65.958,44.635 65.958,44.819 C238.2@66.033,44.894 ; C246.2@67.375,34.986 v2(67.375,36.325) ; R101.2@74.375,56.775 74.425,56.775 74.58,56.93 74.58,57.2 75.08,57.7 75.08,57.725 75.235,57.88 C118.2@75.26,57.88 ; R103.2@80.171,57.961 80.769,57.961 ; R104.2@80.175,55.355 80.69,55.355 80.885,55.55 80.885,55.998 81.061,56.174 ; 81.075,57.136 81.075,57.655 80.769,57.961 ; R248.2@81.107,58.98 80.952,58.825 80.952,58.144 80.769,57.961
  Bottom Layer w0.3: v2(55.146,34.494) 55.165,34.474 55.236,34.474 55.259,34.452 55.612,34.452 55.689,34.375 56.975,34.375 57.123,34.523 57.218,34.523 57.323,34.628 R267.2@57.323,34.723 ; C237.2@56.696,44.325 C236.2@57.35,44.325 v2(58.375,44.325) ; v2@58.386,44.325 v2(58.375,44.325) ; C240.2@58.984,44.85 C240.2@59.025,44.85 ; v2(60.79,44.885) 60.783,44.892 60.372,44.892 59.911,44.431 59.634,44.431 C220.2@59.609,44.406 59.54,44.475 59.54,44.574 59.399,44.715 59.3,44.715 59.19,44.825 59.15,44.825 59.125,44.85 C240.2@59.05,44.85 C240.2@59.025,44.85 ; C118.2@75.26,57.88 v1(75.925,57.88) ; v2(81.325,56.155) 81.306,56.174 81.061,56.174 80.867,56.368 80.867,56.928 81.075,57.136 81.306,57.136 81.325,57.155 C128.2@82.015,57.155 ; v2(58.375,44.325) 58.394,44.344 58.394,44.53 58.689,44.825 59.025,44.825 C240.2@59.025,44.85
  other v1: 28.813,33.825 30.538,33.825
3V3: C35.2 C36.2 L4.2 R52.2 R56.2 | length 17.6
  Top Layer w0.2: R56.2@16.026,20.782 16.051,20.757 v1@16.051,20.107 ; v1@19.251,26.232 C36.2@20.626,26.232 ; R52.2@23.726,20.282 v1(24.301,20.282)
  Bottom Layer w0.2: v1@16.05,20.325 16.05,21.643 19.226,24.819 v1(19.226,26.232) ; v1(21.926,27.057) 21.926,24.857 24.301,22.482 v1(24.301,20.282) 24.301,20.251 v1@24.3,20.25
  other v1: 16.051,20.082 20.601,27.057 21.264,27.057
5V_VIN: C29.2 C32.2 C38.2 C39.2 C42.1 C56.2 C123.2 C147.1 C209.2 C213.2 C214.2 R210.1 U26.3 U26.4 U26.14 U26.15 U26.30 U26.34 U26.35 U54.1 U54.6 | length 27.7
  Top Layer w0.2: R210.1@11.386,37.915 11.386,38.449 12.244,39.307 v1@12.244,39.994 ; C56.2@23.938,35.969 23.938,36.412 24.898,37.372 U26.34@24.898,38.754 ; C29.2@25.288,45.789 25.288,45.139 25.678,44.749 U26.15@25.678,43.524 ; U26.14@26.078,43.524 26.078,44.695 26.563,45.18 C38.2@26.563,45.989 ; U26.3@27.938,40.144 29.133,40.144 v1(29.888,39.389)
  Top Layer w0.3: v1@12.25,40 12.25,40.902 12.25,40.906 v1@12.25,41.8 ; v1@12.275,43.563 12.275,44.463 v1@12.275,45.363
  Top Layer w0.35: C213.2@17.101,23.132 17.176,23.057 U54.1@17.926,23.057
  Top Layer w0.4: v1(16.376,23.082) C213.2@17.101,23.082
  Top Layer w0.5: C147.1@10.686,39.994 12.244,39.994 v1@12.269,39.994 ; C147.1@10.686,40.906 12.25,40.906 v1@12.269,40.906 ; C147.1@10.686,41.806 v1@12.269,41.806 ; C42.1@10.686,43.557 v1@12.269,43.557 ; C42.1@10.686,44.468 v1@12.269,44.468 ; C42.1@10.686,45.368 v1@12.269,45.368
  other v1: 21.601,21.057 22.251,21.057 13.176,21.352 12.476,22.727 22.988,35.219 22.988,36.014 21.986,38.385 22.786,38.385 30.738,39.069 31.438,39.069 12.251,40.002 12.251,40.902 12.251,41.802 12.276,43.565 12.276,44.465 12.276,45.365 27.525,46.05 24.45,46.125 27.775,46.75 24.111,46.81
